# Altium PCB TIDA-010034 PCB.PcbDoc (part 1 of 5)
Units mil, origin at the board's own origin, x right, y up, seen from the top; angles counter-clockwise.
Board outline 4497.63 x 4881.81 mil, 4 copper layers (Top Layer, Signal Layer 1, Signal Layer 2, Bottom Layer), stack 62.18 mil thick; 483 components, 240 nets, 1255 pads, 589 vias.
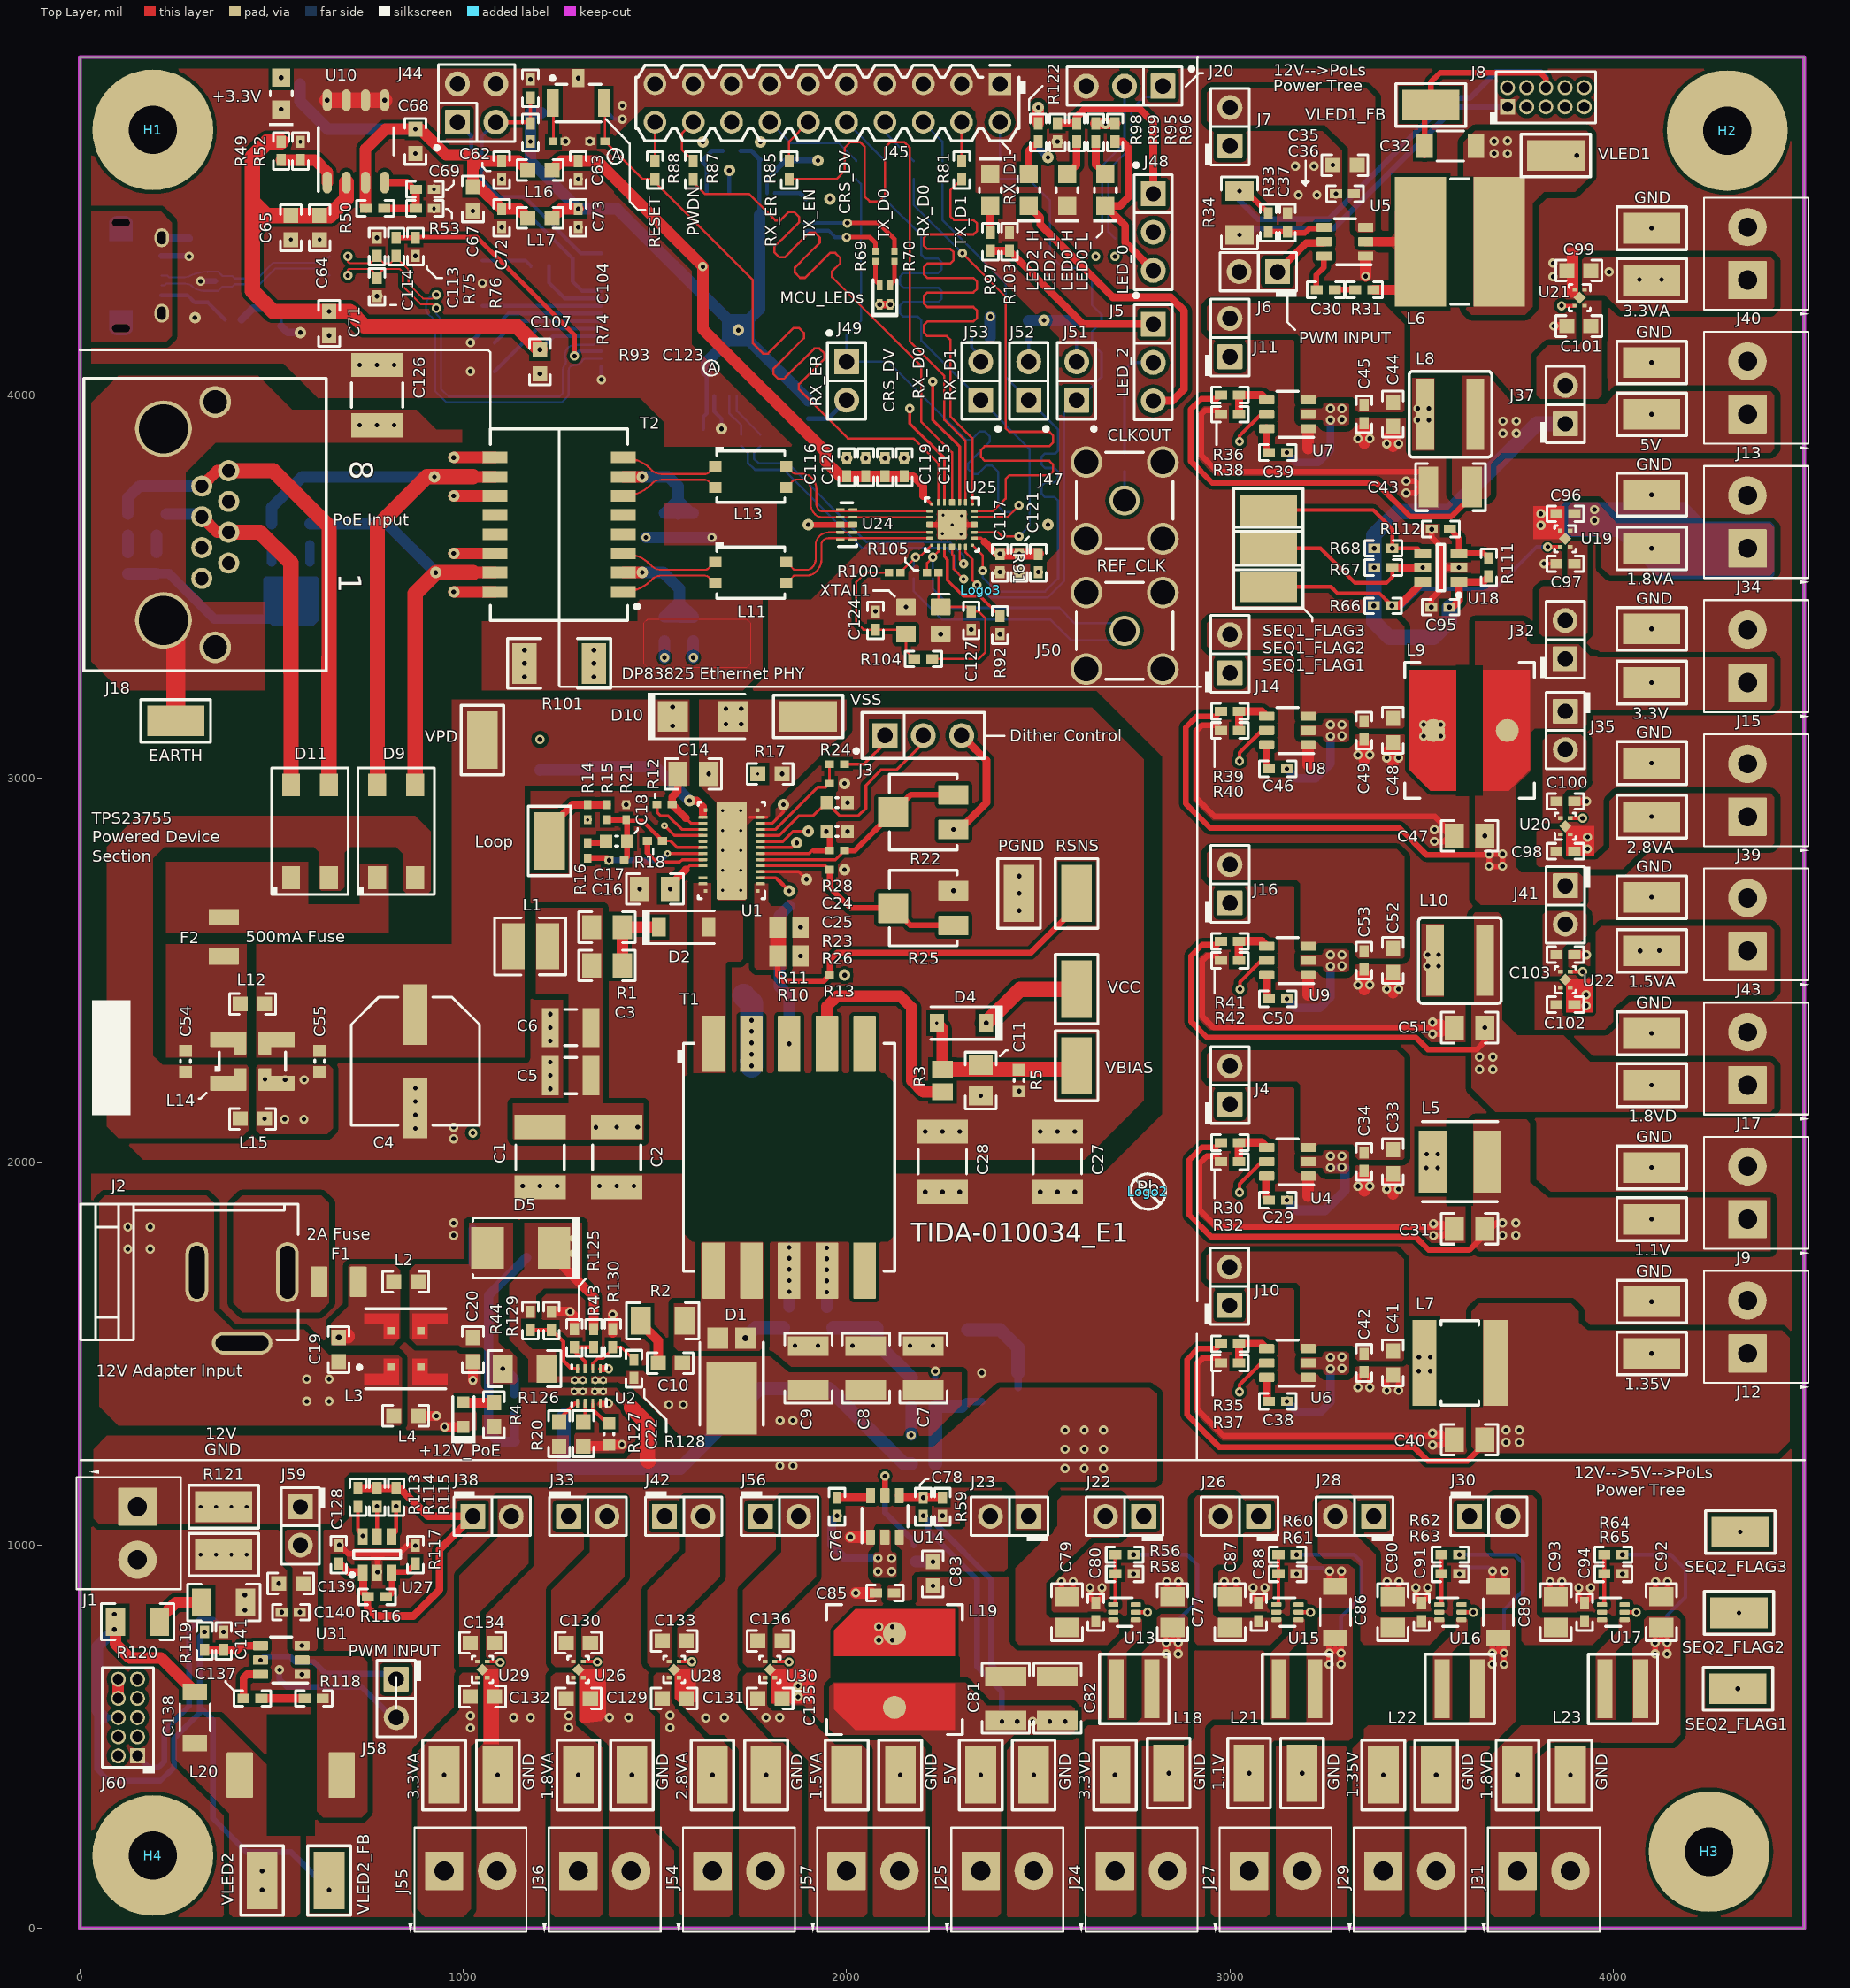
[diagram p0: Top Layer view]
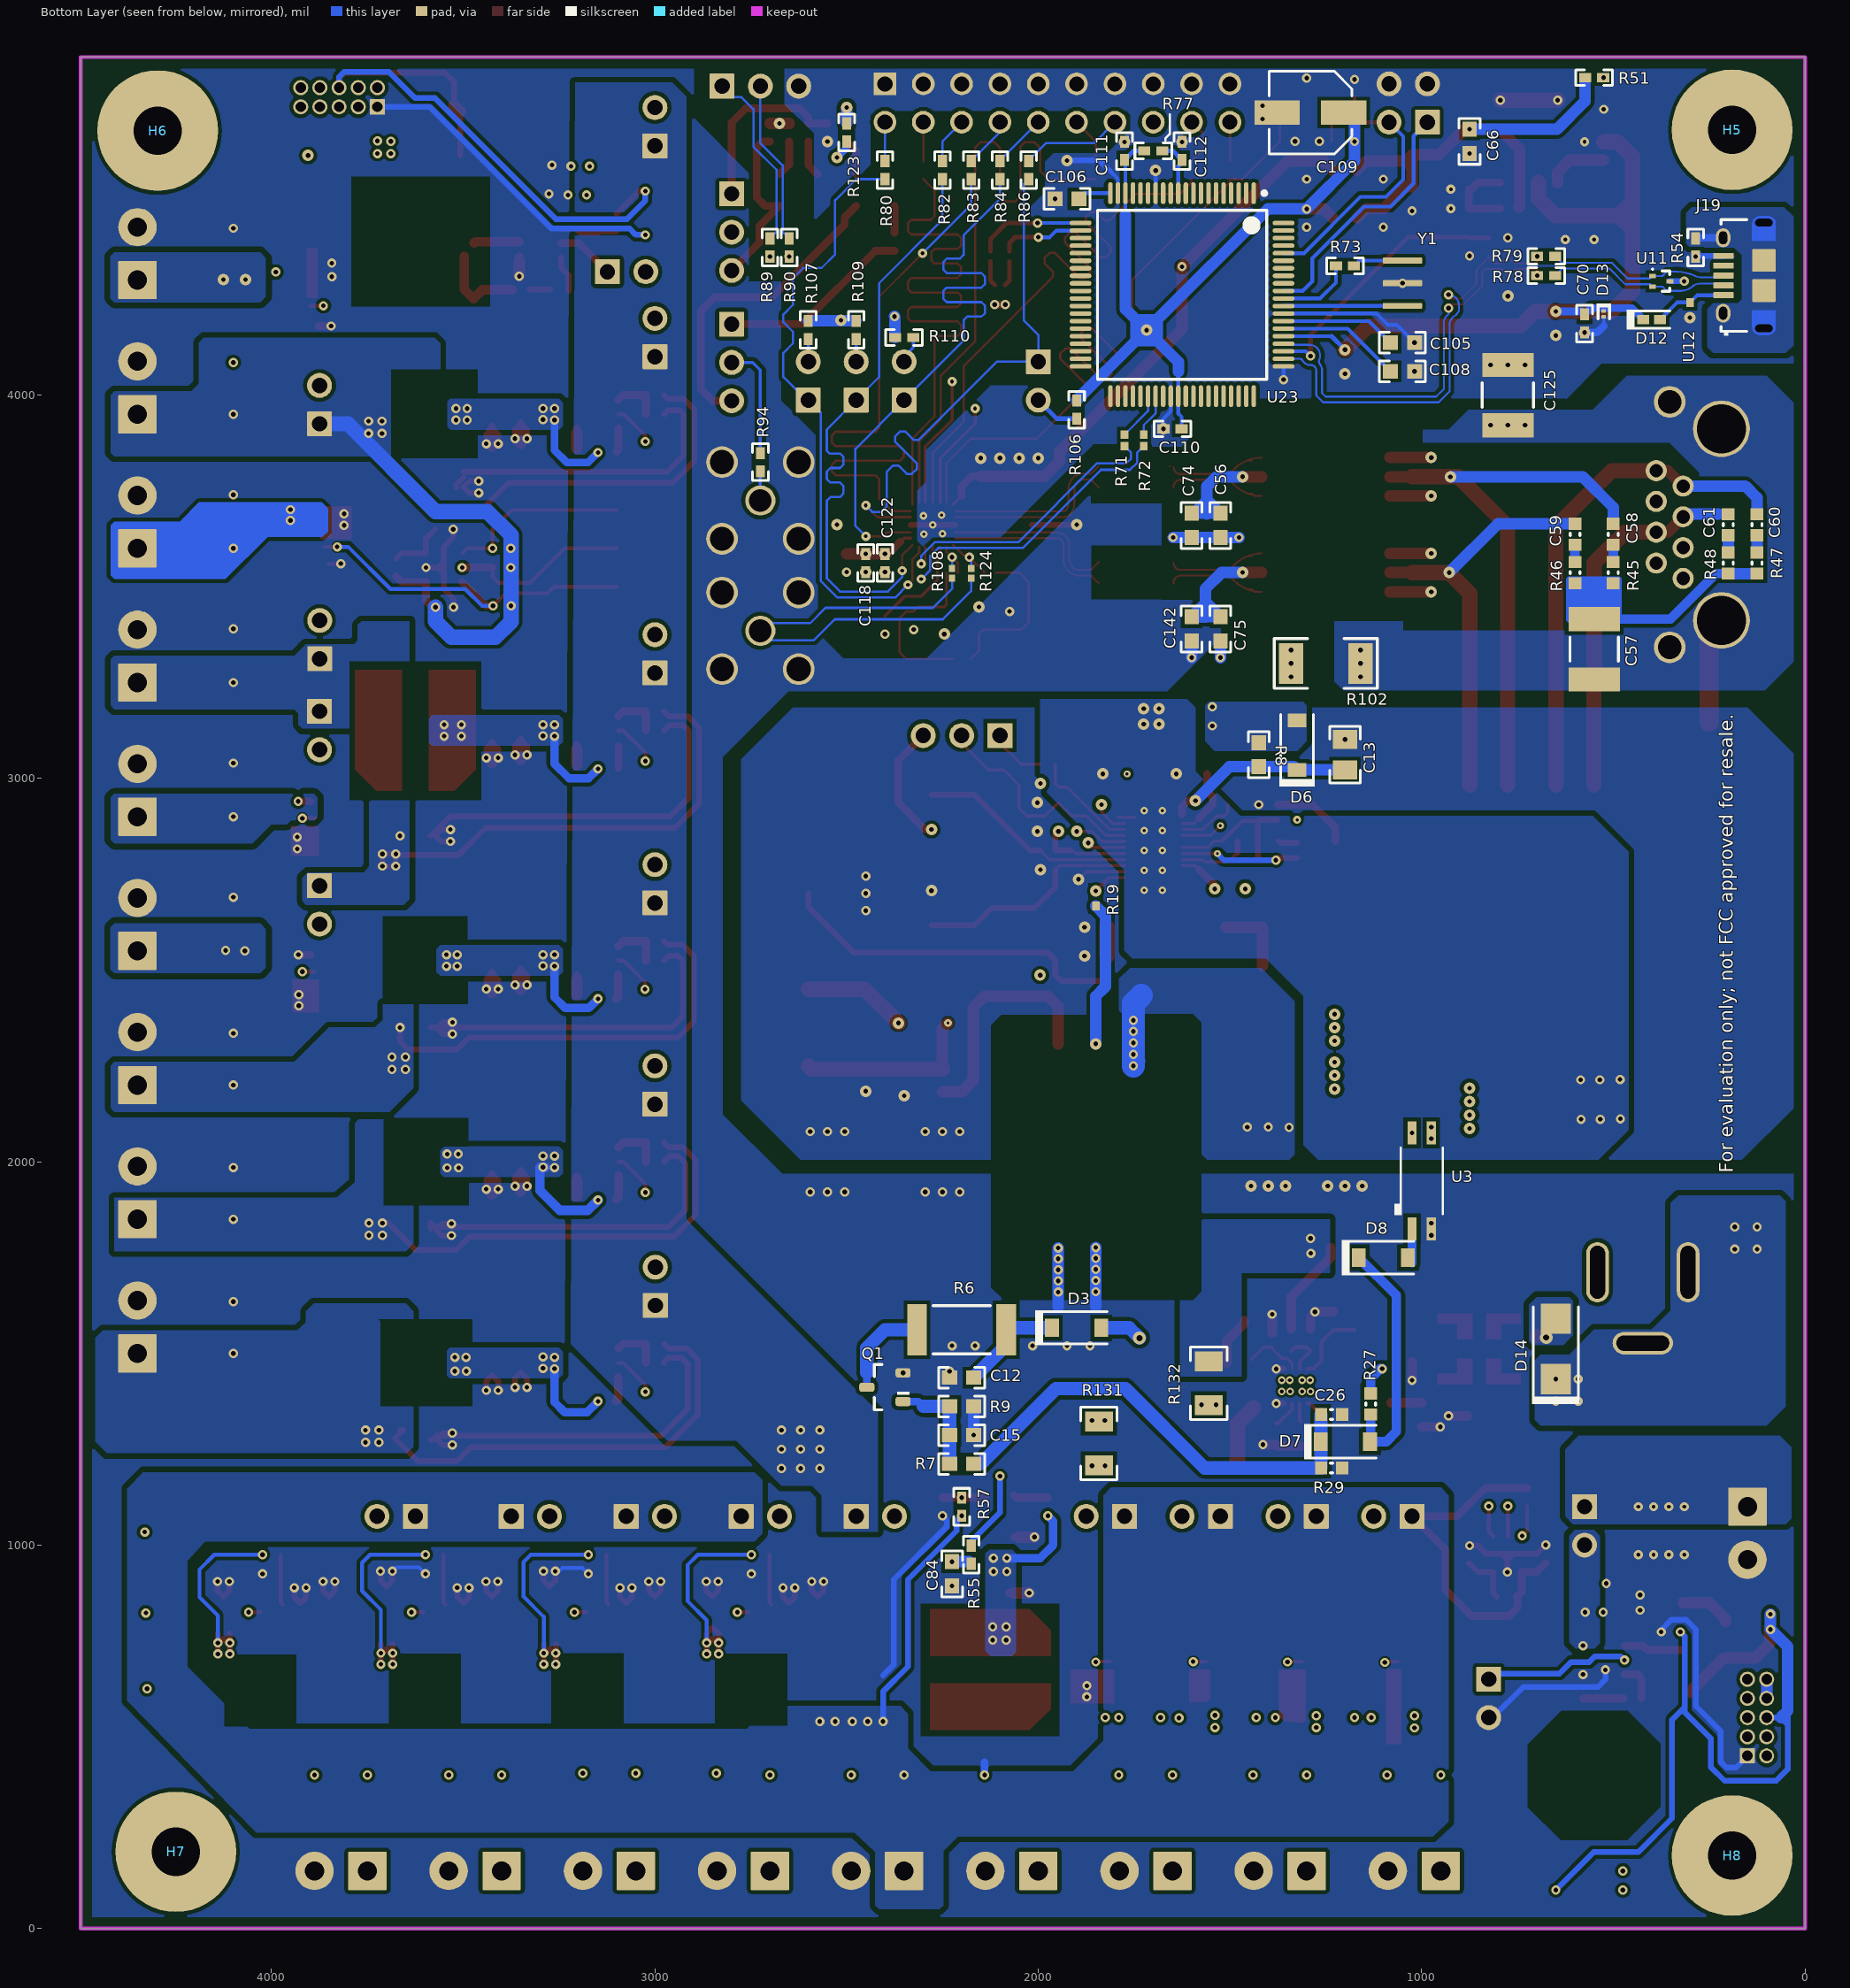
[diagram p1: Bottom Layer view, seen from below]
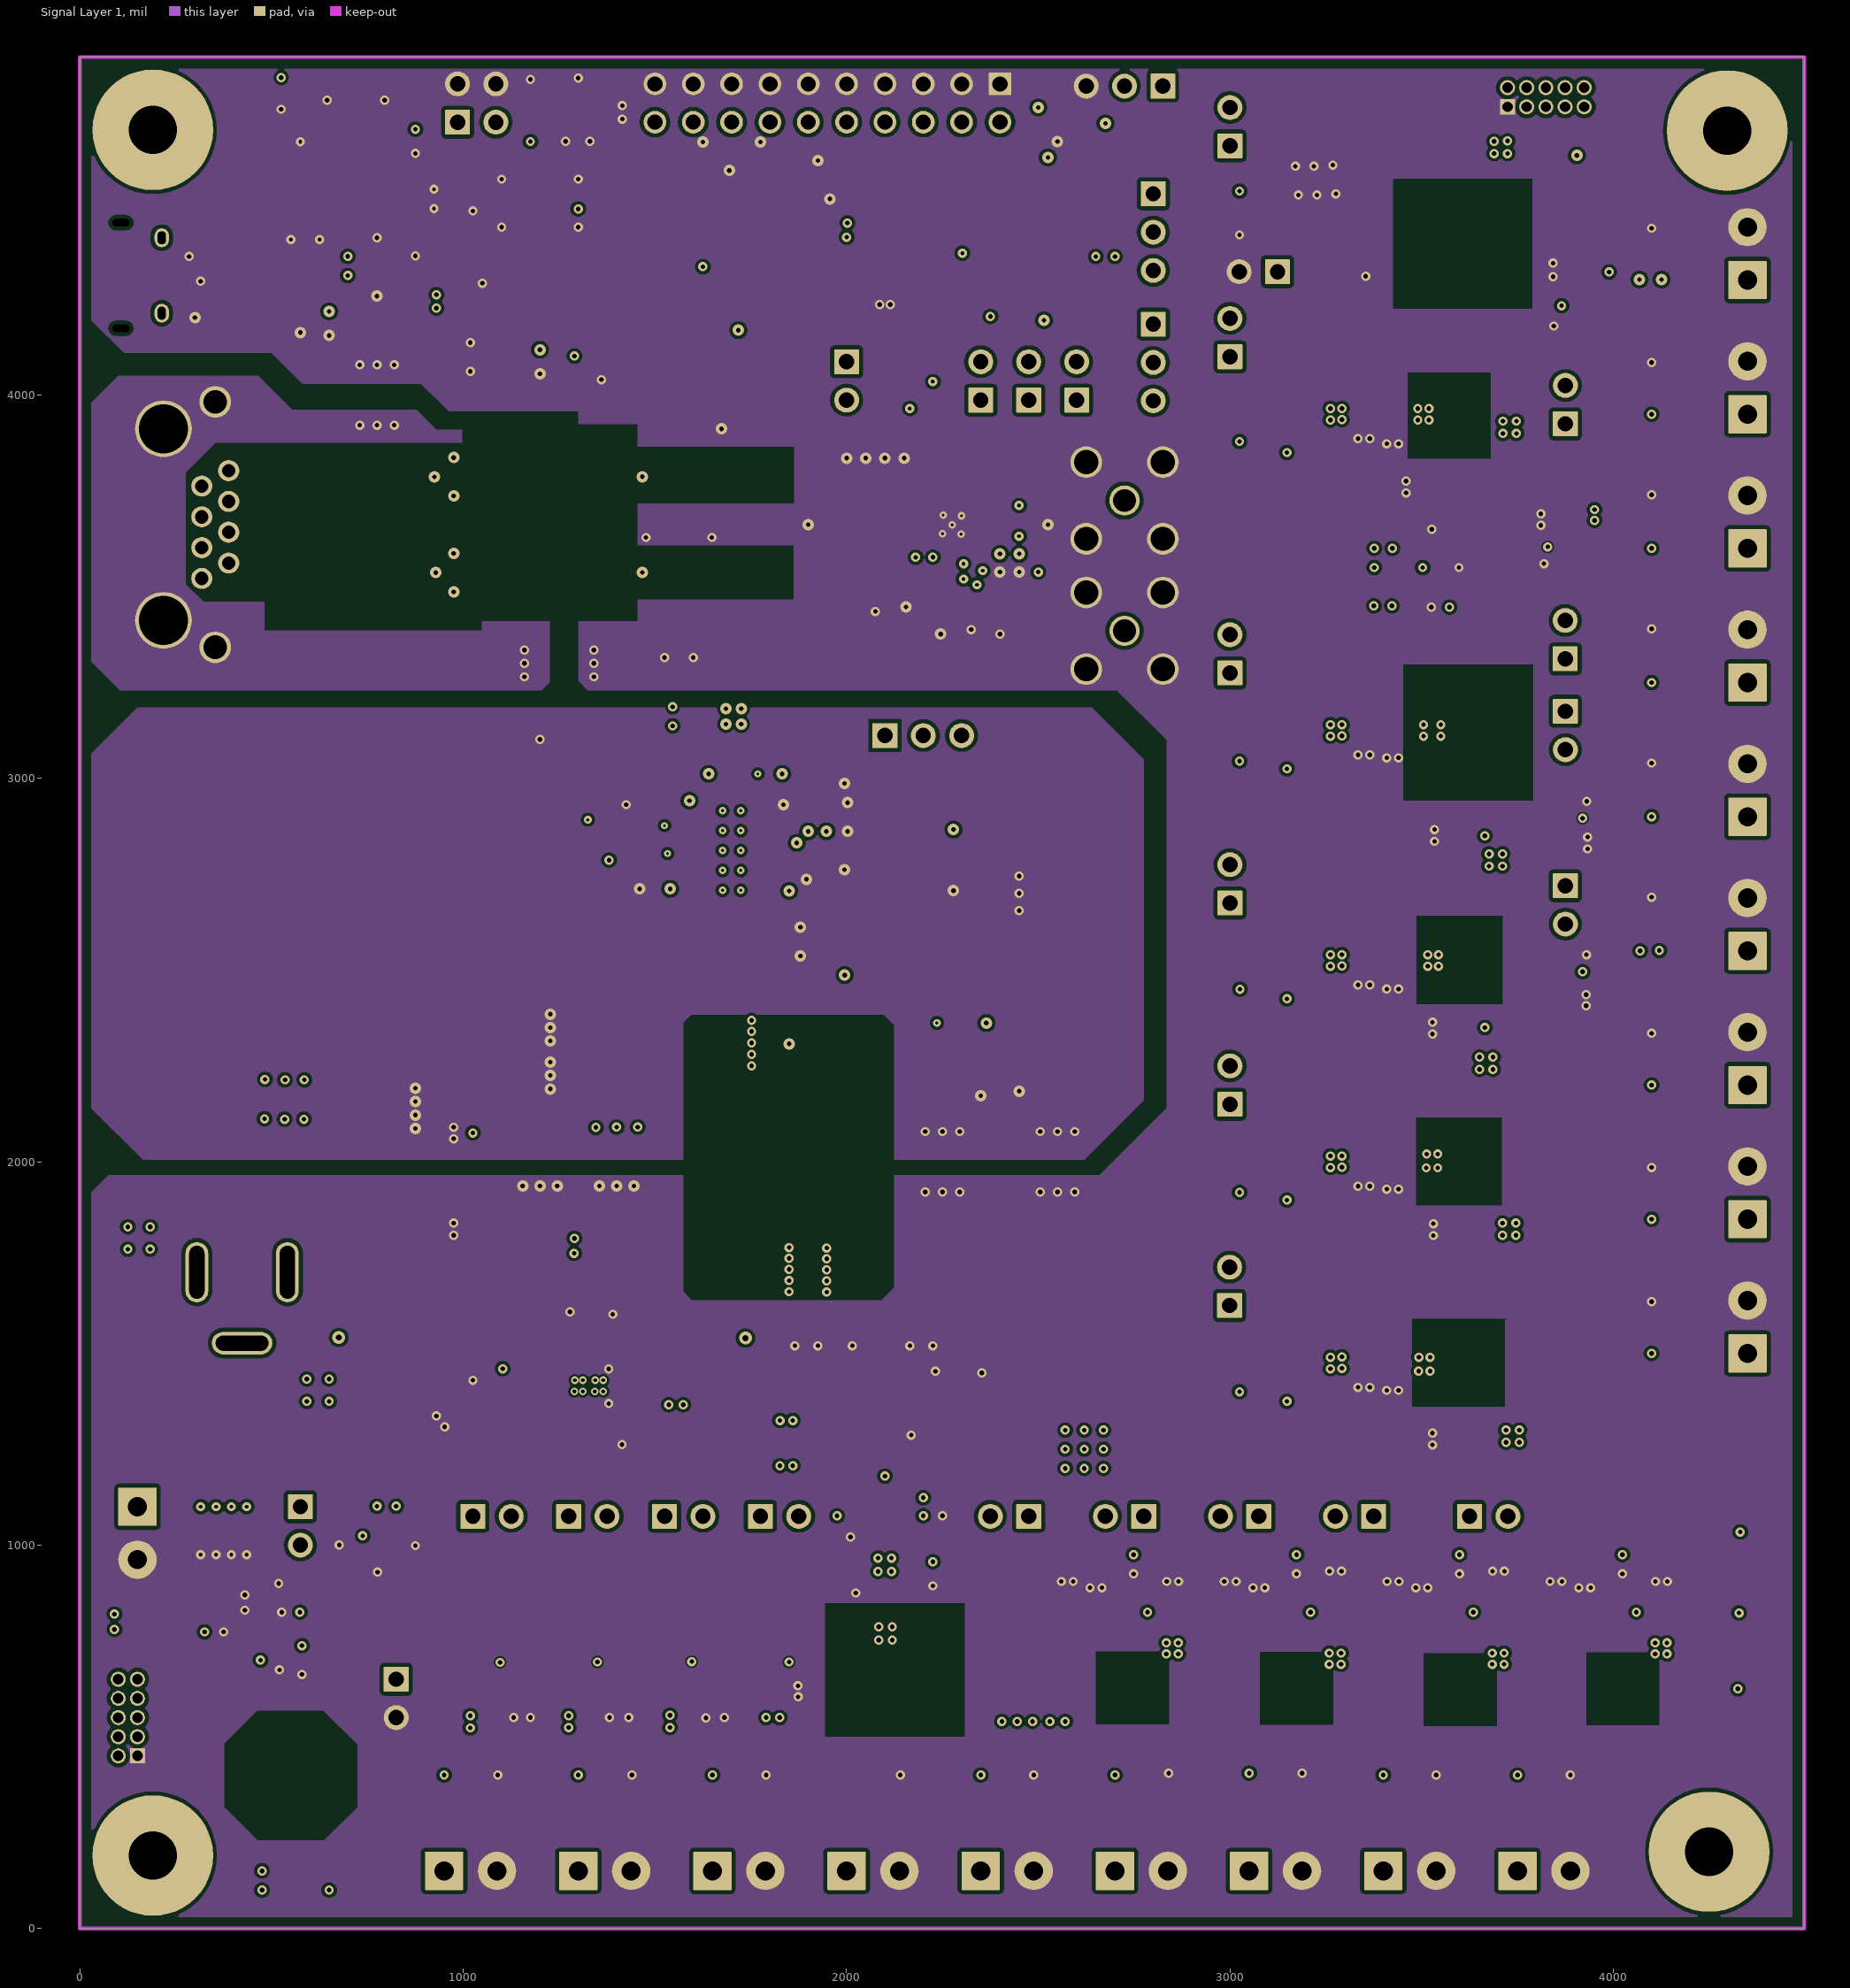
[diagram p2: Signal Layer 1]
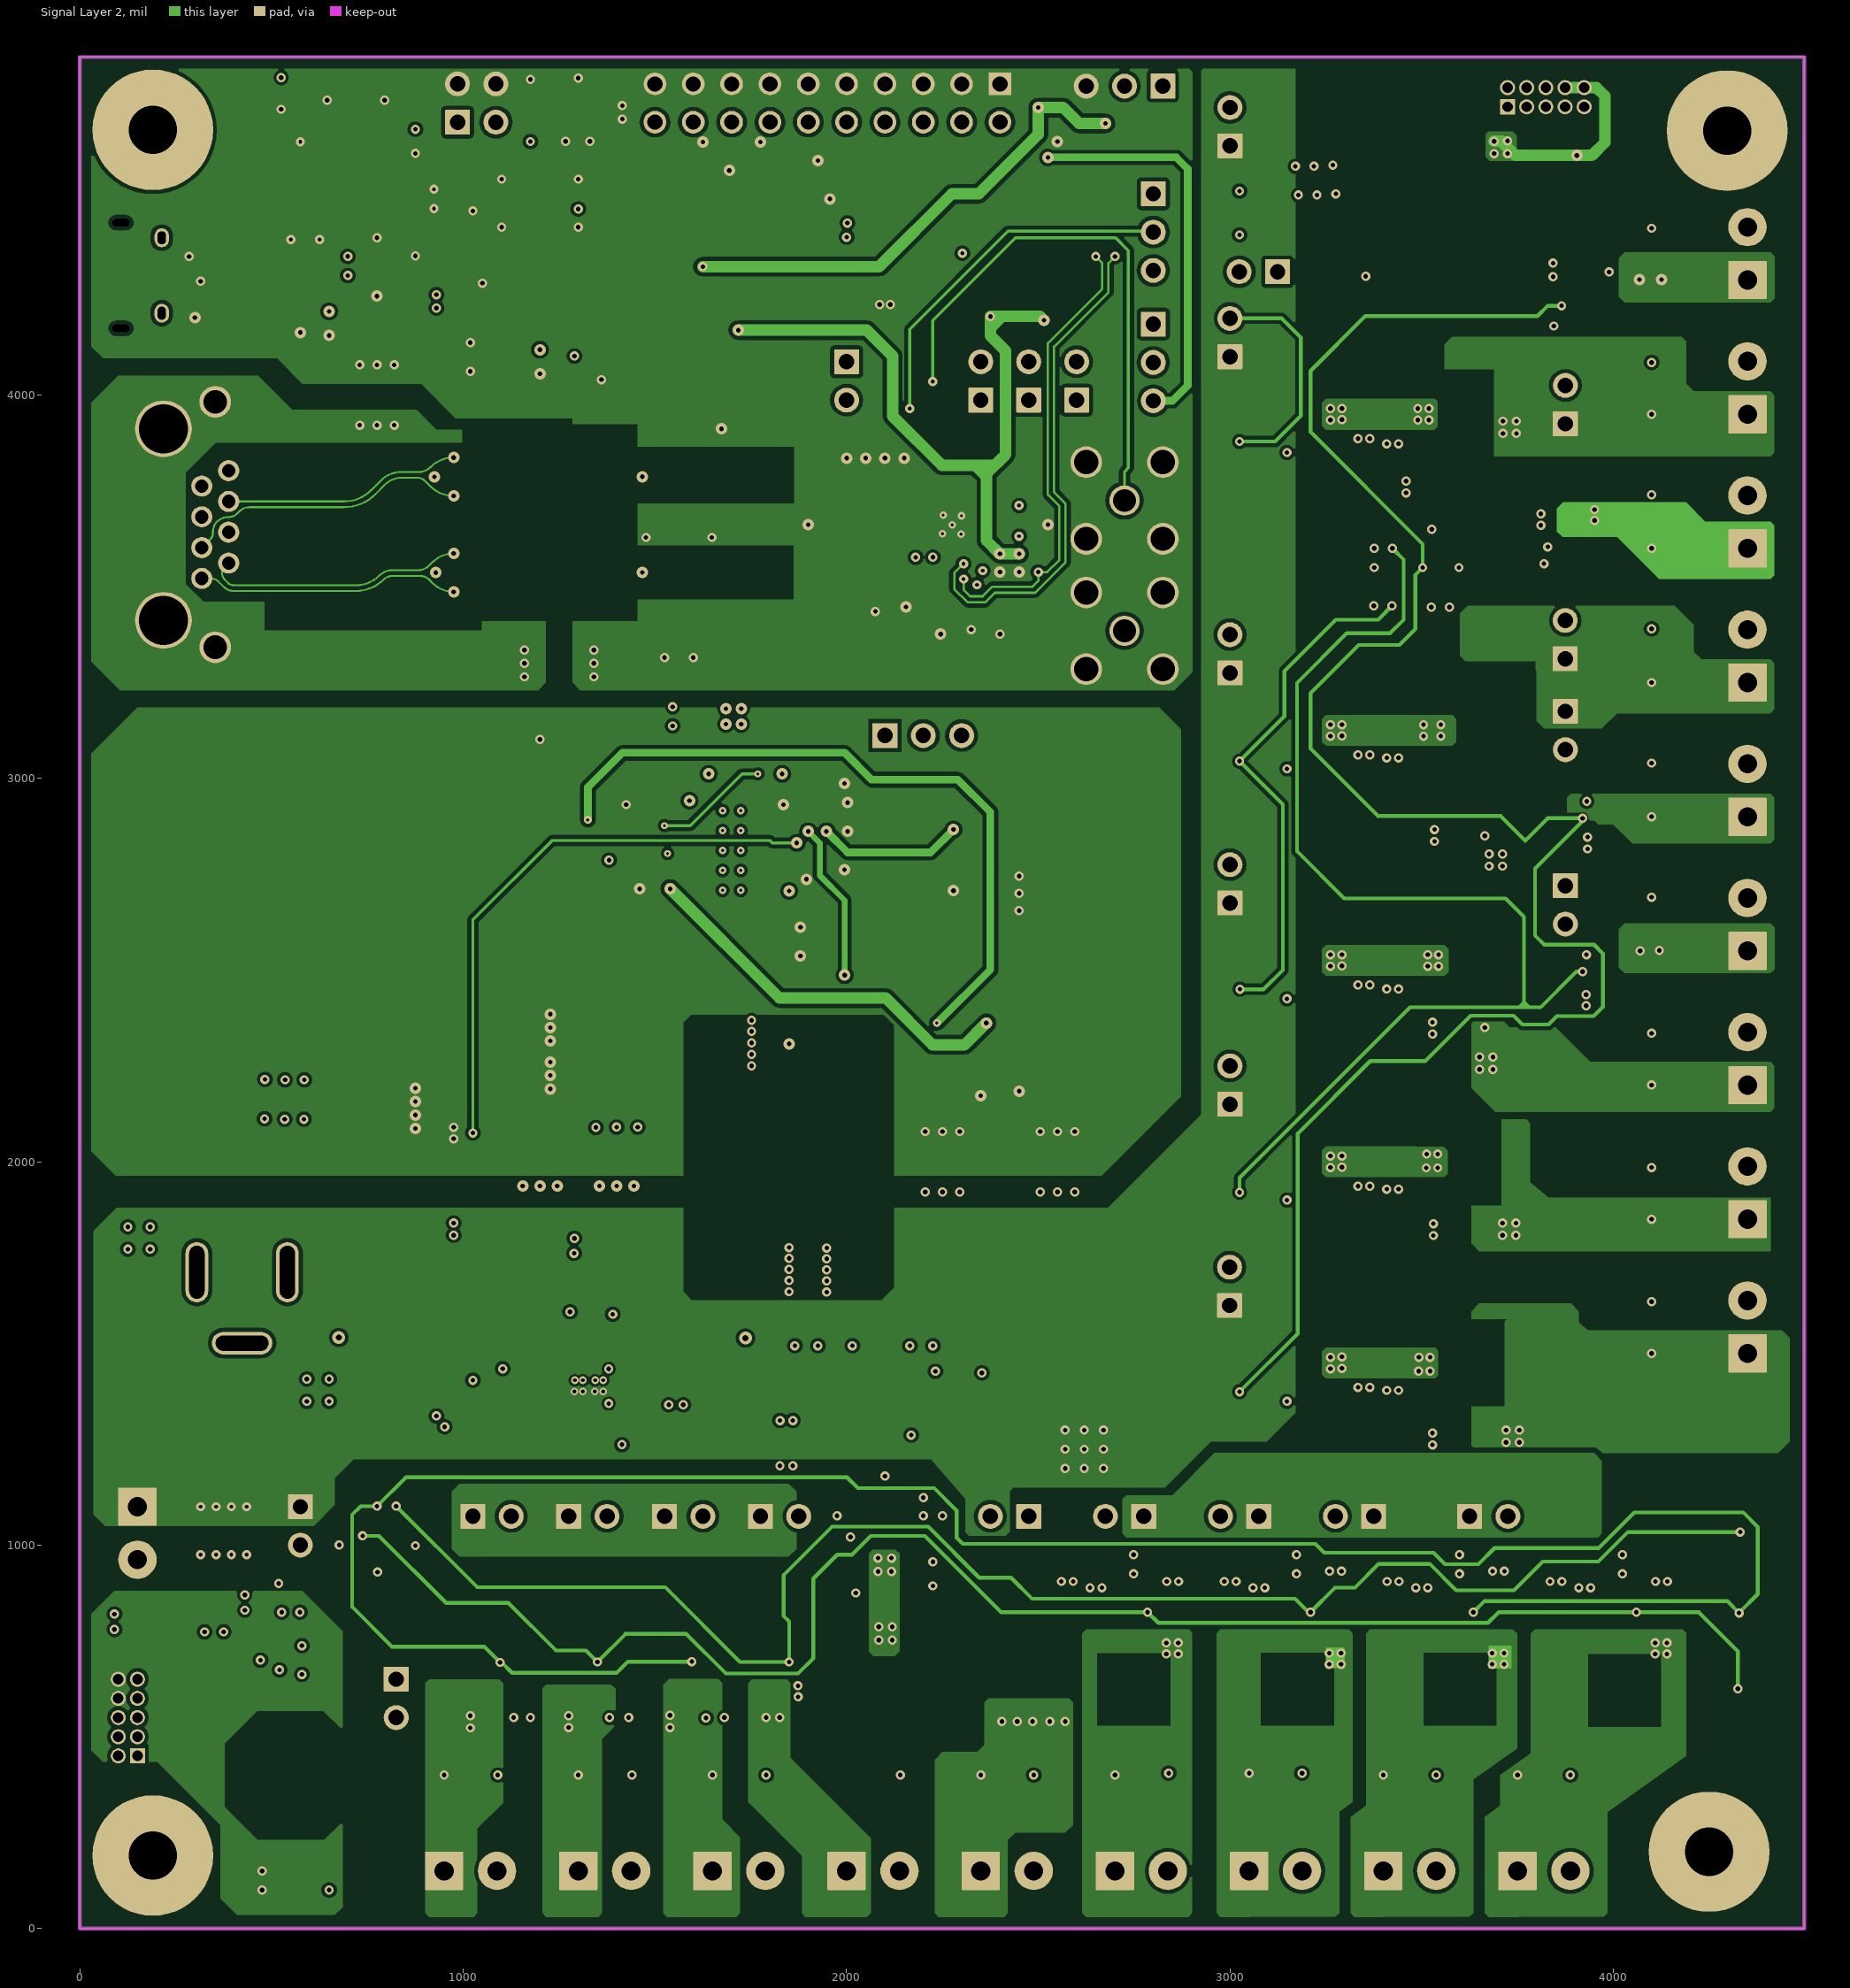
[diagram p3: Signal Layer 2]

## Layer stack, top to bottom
Top Solder: solder mask 0.4, Solder Resist, Dk 3.5
Top Layer: signal copper 1.89
Dielectric1: core 4.2, FR-4, Dk 4.8
Signal Layer 1: signal copper 1.378
Dielectric 2: core 47.244, FR-4, Dk 4.8
Signal Layer 2: signal copper 1.378
Dielectric 3: core 4.2, FR-4, Dk 4.8
Bottom Layer: signal copper 1.89
Bottom Solder: solder mask 0.4, Solder Resist, Dk 3.5

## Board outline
0,0 0,4881.81 4497.63,4881.81 4497.63,0

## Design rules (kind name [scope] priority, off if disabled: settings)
AcuteAngle [All] p1: minimum=4.50000000000000E+0001 checktracksonly=FALSE
AssemblyTestPointUsage [All] p1: valid=2
BoardOutlineClearance BoardOutlineClearance_MountingHoles [OnCopper and InComponentClass('Mounting Holes')] p1: gap=30 ignorepadtopadclearanceinfootprint=FALSE
BoardOutlineClearance BoardOutlineClearance_Poly [OnCopper and IsPoly] p2: gap=25 ignorepadtopadclearanceinfootprint=FALSE
BoardOutlineClearance [OnCopper and Not InComponentClass('Logo') and not InComponentClass('FiducialMark') and not InRegion(1000,500,4000,800) and not InPoly] p3: gap=25 ignorepadtopadclearanceinfootprint=FALSE
Clearance Clearance_U2 [WithinRoom('RoomDefinition_U2')] p1: gap=6 ignorepadtopadclearanceinfootprint=FALSE
Clearance Clearance_U19_U20_U21_U22 [WithinRoom('RoomDefinition_U21')or WithinRoom('RoomDefinition_U19')or WithinRoom('RoomDefinition_U20')or WithinRoom('RoomDefinition_U22')] p2: gap=4 ignorepadtopadclearanceinfootprint=FALSE
Clearance Clearance_U26_U28_U29_U30 [WithinRoom('RoomDefinition_U28')or WithinRoom('RoomDefinition_U30')or WithinRoom('RoomDefinition_U26')or WithinRoom('RoomDefinition_U29')] p3: gap=4 ignorepadtopadclearanceinfootprint=FALSE
Clearance Clearance_4 [InNet('PGND') And OnLayer('Multi-Layer')] p4: gap=10 ignorepadtopadclearanceinfootprint=FALSE except(0: Arc-Hole Track-Hole SMDPad-Hole THPad-Hole Via-Hole Fill-Hole Poly-Hole Region-Hole Text-Hole; 15: Poly-Poly)
Clearance "Keepout to all" [IsKeepOut] p5: gap=25 ignorepadtopadclearanceinfootprint=FALSE except(0: Arc-Hole Track-Hole SMDPad-Hole THPad-Hole Via-Hole Fill-Hole Poly-Hole Region-Hole Text-Hole)
Clearance Clearance_2 [InNamedPolygon('TOP_LAYER_DRAIN_P010')] p6: gap=10 ignorepadtopadclearanceinfootprint=FALSE except(0: Arc-Hole Track-Hole SMDPad-Hole THPad-Hole Via-Hole Fill-Hole Poly-Hole Region-Hole Text-Hole; 8: Via-Fill Via-Poly Via-Region; 15: Fill-Fill Fill-Poly Fill-Region Poly-Poly Poly-Region Region-Region)
Clearance Clearance_1 [InNamedPolygon('TOP_LAYER_RSNS_P008') And OnLayer('Top Layer')] p7: gap=10 ignorepadtopadclearanceinfootprint=FALSE except(0: Arc-Hole Track-Hole SMDPad-Hole THPad-Hole Via-Hole Fill-Hole Poly-Hole Region-Hole Text-Hole; 8: Via-Fill Via-Poly Via-Region; 15: Fill-Fill Fill-Poly Fill-Region Poly-Poly Poly-Region Region-Region)
Clearance Clearance_Keepouts [((IsTrack Or IsArc) And Not InPoly) And IsFree and IsKeepOut vs ((IsTrack Or IsArc) And Not InPoly) And IsFree and IsKeepOut] p8: gap=0 ignorepadtopadclearanceinfootprint=FALSE
Clearance Clearance_Poly [InPolygon] p9: gap=10 ignorepadtopadclearanceinfootprint=FALSE except(0: Arc-Hole Track-Hole SMDPad-Hole THPad-Hole Via-Hole Fill-Hole Poly-Hole Region-Hole Text-Hole; 8: Via-Poly; 15: Poly-Poly)
Clearance Clearance_FiducialMark [IsKeepOut and InComponentClass('FiducialMark') vs IsPad and InComponentClass('FiducialMark')] p10: gap=0 ignorepadtopadclearanceinfootprint=FALSE
Clearance [All] p11: gap=7.87 ignorepadtopadclearanceinfootprint=FALSE except(0: Arc-Hole Track-Hole SMDPad-Hole THPad-Hole Via-Hole Fill-Hole Poly-Hole Region-Hole Text-Hole; 4.7: SMDPad-SMDPad; 15: Fill-Fill Fill-Poly Fill-Region Poly-Poly Poly-Region Region-Region)
ComponentClearance ComponentClearance_MountingHoles_FiducialMarks [InComponentClass('Mounting Holes') vs InComponentClass('FiducialMark')] p1: gap=10 collisioncheckmode=3 verticalgap=10 showdistances=FALSE
ComponentClearance ComponentClearance_Shunt [InComponentClass('Header') vs InComponentClass('Shunt')] p2: gap=0 collisioncheckmode=3 verticalgap=0 showdistances=FALSE
ComponentClearance ComponentClearance_Logo [InComponentClass('Logo')] p3: gap=10 collisioncheckmode=3 verticalgap=10 showdistances=FALSE
ComponentClearance ComponentClearance_ScrewToNut [(HasFootprint('NY PMS 440 0025 PH')) vs (HasFootprint('Keystone_1902C'))] p4: gap=5 collisioncheckmode=3 verticalgap=10 showdistances=FALSE
ComponentClearance ComponentClearance_MountingHoles [InComponentClass('Mounting Holes')] p5: gap=10 collisioncheckmode=3 verticalgap=100000 showdistances=FALSE
ComponentClearance ComponentClearance_SmallPassives [HasFootprint('0201*') or HasFootprint('0402*') or HasFootprint('0508') or HasFootprint('0603*') or HasFootprint('0612') or HasFootprint('0805*') or HasFootprint('0815*') or HasFootprint('0830*') or HasFootprint('1206*') or HasFootprint('1210*') or HasFootprint('1808*') or HasFootprint('1812*') or HasFootprint('1825*') or HasFootprint('2010*') or HasFootprint('2220*') or HasFootprint('2225*') or HasFootprint('2512*') or HasFootprint('2728*') or HasFootprint('3518*') vs HasFootprint('0201*') or HasFootprint('0402*') or HasFootprint('0508') or HasFootprint('0603*') or HasFootprint('0612') or HasFootprint('0805*') or HasFootprint('0815*') or HasFootprint('0830*') or HasFootprint('1206*') or HasFootprint('1210*') or HasFootprint('1808*') or HasFootprint('1812*') or HasFootprint('1825*') or HasFootprint('2010*') or HasFootprint('2220*') or HasFootprint('2225*') or HasFootprint('2512*') or HasFootprint('2728*') or HasFootprint('3518*')] p6: gap=10 collisioncheckmode=3 verticalgap=10 showdistances=FALSE
ComponentClearance ComponentClearance_THtoSMT [IsThruComponent vs IsSMTComponent] p7: gap=10 collisioncheckmode=3 verticalgap=10 showdistances=FALSE
ComponentClearance ComponentClearance_THtoTH [IsThruComponent vs IsThruComponent] p8: gap=10 collisioncheckmode=3 verticalgap=10 showdistances=FALSE
ComponentClearance [All] p9: gap=10 collisioncheckmode=3 verticalgap=10 showdistances=FALSE
DiffPairsRouting [All] p1: maxlimit=10 minlimit=10 mostfreqgap=10 toplayer_minwidth=5 toplayer_maxwidth=5 toplayer_prefwidth=5 midlayer1_minwidth=5 midlayer1_maxwidth=5 midlayer1_prefwidth=5 midlayer2_minwidth=5 midlayer2_maxwidth=5 midlayer2_prefwidth=5 bottomlayer_minwidth=5 bottomlayer_maxwidth=5 bottomlayer_prefwidth=5 maxuncoupledlength=1000
FabricationTestPointUsage TestPointUsage [All] p1: valid=2 allowmultiple=FALSE
FabricationTestpoint Testpoint [All] p1: side=3 testpointundercomponent=TRUE minsize=40 maxsize=100 preferedsize=60 minholesize=0 maxholesize=40 preferedholesize=32 testpointgrid=1 allowsidetop=TRUE allowsidebottom=TRUE usegrid=TRUE gridtolerance=0.01
FanoutControl Fanout_LCC [IsLCC] p1: bgadir=Out bgaviamode=Centered fanoutstyle=Auto fanoutdirection=Alternating viagrid=1 // Fanout_LCC (Default Rule)
FanoutControl Fanout_BGA [IsBGA] p2: bgadir=Out bgaviamode=Centered fanoutstyle=Auto fanoutdirection=Alternating viagrid=1 // Fanout_BGA (Default Rule)
FanoutControl Fanout_Default [All] p4: bgadir=Out bgaviamode=Centered fanoutstyle=Auto fanoutdirection=Alternating viagrid=1 // Fanout_Default (Default Rule)
FanoutControl Fanout_Small [(CompPinCount < 5)] p5: bgadir=Out bgaviamode=Centered fanoutstyle=Auto fanoutdirection=OutThenIn viagrid=1 // Fanout_Small (Default Rule)
HoleSize [All] p1: absolutevalues=TRUE maxlimit=251 minlimit=7.87 maxpercent=80.000 minpercent=20.000
MatchedLengths "Length Matching" [InNetClass('Length match')] p1: tolerance=20 checknetsindiffpair=FALSE checkdiffpairvsdiffpair=TRUE checkxsignals=TRUE checkothers=TRUE
MinimumAnnularRing MinimumAnnularRing_ThermalPadVias [IsVia and InAnyComponent] p1: minimumring=5.91
MinimumAnnularRing [All] p2: minimumring=8
MinimumSolderMaskSliver MinimumSolderMaskSliver_Logo [InComponentClass('Logo') vs InComponentClass('Logo')] p1: minsoldermaskwidth=0.7
MinimumSolderMaskSliver [All] p2: minsoldermaskwidth=3.94
PlaneConnect [All] p1: planeconnectstyle=Relief reliefexpansion=10 reliefentries=4 reliefconductorwidth=10 reliefairgap=10
PolygonConnect [All] p1: connectstyle=Direct reliefconductorwidth=10 reliefentries=4 polygonreliefangle="90 Angle" airgapwidth=10
RoomDefinition RoomDefinition_U2 [All] p1: confinementstyle=ConfineOut formatcopy=TRUE lockcomponents=FALSE outline 1400,1350 1250,1350 1250,1480 1400,1480
RoomDefinition [All vs False] p2: confinementstyle=ConfineOut formatcopy=TRUE lockcomponents=FALSE outline 1250,1480.41
RoomDefinition RoomDefinition_U22 [All] p3: confinementstyle=ConfineOut formatcopy=TRUE lockcomponents=FALSE outline 3840,2510 3919.72,2510 3919.72,2430 3840,2430
RoomDefinition RoomDefinition_U20 [All] p4: confinementstyle=ConfineOut formatcopy=TRUE lockcomponents=FALSE outline 3840,2915 3929.88,2915 3929.88,2840 3840,2840
RoomDefinition RoomDefinition_U19 [InComponentClass('Components Class 4')] p5: confinementstyle=ConfineIn formatcopy=TRUE lockcomponents=FALSE outline 3820,3664.71 3926,3664.71 3926,3580 3820,3580
RoomDefinition RoomDefinition_U21 [InComponentClass('Components Class 3')] p6: confinementstyle=ConfineIn formatcopy=TRUE lockcomponents=FALSE outline 3870,4298.62 3955,4298.62 3955,4210 3870,4210
RoomDefinition RoomDefinition_U30 [All] p7: confinementstyle=ConfineOut formatcopy=TRUE lockcomponents=FALSE outline 1740,720 1865,720 1865,640 1740,640
RoomDefinition RoomDefinition_U28 [All] p8: confinementstyle=ConfineOut formatcopy=TRUE lockcomponents=FALSE outline 1500,720 1610,720 1610,640 1500,640
RoomDefinition RoomDefinition_U26 [InComponentClass('Components Class 2')] p9: confinementstyle=ConfineIn formatcopy=TRUE lockcomponents=FALSE outline 1240.02,720 1369.69,720 1369.69,630 1240.02,630
RoomDefinition RoomDefinition_U29 [InComponent('U29')] p10: confinementstyle=ConfineOut formatcopy=TRUE lockcomponents=FALSE outline 982,620 1125.16,620 1125.16,721 982,721
RoutingVias ThermalPadVias [IsVia and InAnyComponent] p1: holewidth=7.87 width=19.68 viastyle="Through Hole" minholewidth=7.87 minwidth=19.68 maxholewidth=12.99 maxwidth=23.62
RoutingVias [All] p2: holewidth=12 width=24 viastyle="Through Hole" minholewidth=7.87 minwidth=20 maxholewidth=40 maxwidth=65
SilkToBoardRegionClearance [Not ((IsComment or IsDesignator) And (Hide <> 'False')) and not InRegion(1000,500,4000,800)] p1:
SilkToSilkClearance SilkToSilkClearance_Pb-FreeLogo [(HasFootprint('Pb-Free_Overlay_Medium') OR HasFootprint('Pb-Free_Overlay_Small')) vs (HasFootprint('Pb-Free_Overlay_Medium') OR HasFootprint('Pb-Free_Overlay_Small'))] p1: silktosilkclearance=0
SilkToSilkClearance [All] p2: silktosilkclearance=4
SilkToSolderMaskClearance SilkToComponentPadClearance [(IsPad or IsFill or IsRegion) and InAnycomponent] p1: minsilkscreentomaskgap=5 clearancetoexposedcopper=TRUE
SilkToSolderMaskClearance "Silk to Solder Mask Opening" [All] p2: minsilkscreentomaskgap=4 clearancetoexposedcopper=FALSE
SolderMaskExpansion [All] p1: expansion=1.97
Width [All] p1: maxlimit=100 minlimit=5 preferedwidth=10 minimp=50.000000 maximp=50.000000 favimp=50.000000 checkconnectedcopper=TRUE
15 further rules are at their usual default settings.

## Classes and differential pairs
net class Undefined: 12V
net class "Length match": CRS_DV_S PWDN_S RESET_S RX_D0_S RX_D1_S RX_ER_S TX_D0_S TX_D1_S TX_EN_S
component class "TIDA-010034 DP83825 ETHERNET PHY": C115 C116 C117 C118 C119 C120 C121 C122 C123 C124 C127 J5 J20 J45 J47 J48 J49 J50 J51 J52 J53 LED0_H LED0_L LED2_H LED2_L R80 R81 R82 R83 R84 R85 R86 R87 R88 R89 R90 R91 R92 R93 R94 R95 R96 R97 R98 R99 R100 R103 R104 R105 R106 R107 R108 R109 R110 R122 R123 R124 RESET U24 U25 XTAL1
component class "TIDA-010034 MSP430": C104 C105 C106 C107 C108 C109 C110 C111 C112 C113 C114 J44 MCU_LEDs R69 R70 R71 R72 R73 R74 R75 R76 R77 R78 R79 U23 Y1
component class "Mounting Holes": H1 H2 H3 H4
component class "TIDA-010034 Hardware": H1 H2 H3 H4 H5 H6 H7 H8 Logo2 Logo3 ZZ1 ZZ2 ZZ3 ZZ4
component class AssemblyNote: ZZ1 ZZ2 ZZ3 ZZ4
component class Header: J3 J4 J5 J6 J7 J8 J10 J11 J14 J16 J20 J22 J23 J26 J28 J30 J32 J33 J35 J37 J38 J41 J42 J44 J45 J48 J49 J51 J52 J53 J56 J58 J59 J60
component class "TIDA-010034 TPS23755 PD FRONT-END": 12V +12V_PoE C1 C2 C3 C4 C5 C6 C7 C8 C9 C10 C11 C12 C13 C14 C15 C16 C17 C18 C19 C20 C22 C24 C25 C26 C27 C28 D1 D2 D3 D4 D5 D6 D7 D8 D14 F1 GND J1 J2 J3 L1 L2 L3 L4 Loop PGND Q1 R1 R2 R3 R4 R5 R6 R7 R8 R9 R10 R11 R12 R13 R14 R15 R16 R17 R18 R19 R20 R21 R22 R23 R24 R25 R26 R27 R28 R29 R43 R44 R125 R126 R127 R128 R129 R130 R131 R132 RSNS T1 U1 U2 U3 VBIAS VCC
component class "TIDA-010034 PoE INPUT": C54 C55 C56 C57 C58 C59 C60 C61 C74 C75 C125 C126 C142 D9 D10 D11 EARTH F2 J18 L11 L12 L13 L14 L15 R45 R46 R47 R48 R101 R102 T2 VPD VSS
component class "TIDA-010034 12V To POINT OF LOADS": 1.1V 1.5VA 1.8VA 1.8VD 1.35V 2.8VA 3.3V 3.3VA 5V C29 C30 C31 C32 C33 C34 C35 C36 C37 C38 C39 C40 C41 C42 C43 C44 C45 C46 C47 C48 C49 C50 C51 C52 C53 C95 C96 C97 C98 C99 C100 C101 C102 C103 GND J4 J6 J7 J8 J9 J10 J11 J12 J13 J14 J15 J16 J17 J32 J34 J35 J37 J39 J40 J41 J43 L5 L6 L7 L8 L9 L10 R30 R31 R32 R33 R34 R35 R36 R37 R38 R39 R40 R41 R42 R66 R67 R68 R111 R112 SEQ1_FLAG1 SEQ1_FLAG2 SEQ1_FLAG3 U4 U5 U6 U7 U8 U9 U18 U19 U20 U21 U22 VLED1 VLED1_FB
net class Power: VDD1_1.1V VDD1_1.8V_codec VDD1_1.35V VDD1_3.3V VDD1_5V VDD2_1.1V VDD2_1.8V_Codec VDD2_1.35V VDD2_3.3V VDD2_5V
component class "TIDA-010034 12V TO 5V TO POINT OF LOADS": 1.1V 1.5VA 1.8VA 1.8VD 1.35V 2.8VA 3.3VA 3.3VD 5V C76 C77 C78 C79 C80 C81 C82 C83 C84 C85 C86 C87 C88 C89 C90 C91 C92 C93 C94 C128 C129 C130 C131 C132 C133 C134 C135 C136 C137 C138 C139 C140 C141 GND J22 J23 J24 J25 J26 J27 J28 J29 J30 J31 J33 J36 J38 J42 J54 J55 J56 J57 J58 J59 J60 L18 L19 L20 L21 L22 L23 R55 R56 R57 R58 R59 R60 R61 R62 R63 R64 R65 R113 R114 R115 R116 R117 R118 R119 R120 R121 SEQ2_FLAG1 SEQ2_FLAG2 SEQ2_FLAG3 U13 U14 U15 U16 U17 U26 U27 U28 U29 U30 U31 VLED2 VLED2_FB
component class "TIDA-010034 USB INPUT": +3.3V C62 C63 C64 C65 C66 C67 C68 C69 C70 C71 C72 C73 D12 D13 J19 L16 L17 R49 R50 R51 R52 R53 R54 U10 U11 U12
differential pair USB: +USB_P -USB_N
differential pair TD: +TD_P -TD_N
differential pair TARGET_D: +TARGET_D_P -TARGET_D_N
differential pair RD: +RD_P -RD_N
differential pair "netj18_1 & 2": +NetJ18_1 -NetJ18_2
differential pair "NetJ18_3 & 6": +NetJ18_3 -NetJ18_6

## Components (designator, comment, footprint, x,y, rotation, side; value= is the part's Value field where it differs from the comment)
1.1V "TESTPOINT" Keystone_5019 4100,1850 r0 top
1.1V "TESTPOINT" Keystone_5019 3050,405 r270 top
1.5VA "TESTPOINT" Keystone_5019 2000,400 r90 top
1.5VA "TESTPOINT" Keystone_5019 4100,2550 r180 top
1.8VA "TESTPOINT" Keystone_5019 1300,400 r90 top
1.8VA "TESTPOINT" Keystone_5019 4100,3600 r180 top
1.8VD "TESTPOINT" Keystone_5019 4100,2200 r180 top
1.8VD "TESTPOINT" Keystone_5019 3750,400 r270 top
1.35V "TESTPOINT" Keystone_5019 4100,1500 r0 top
1.35V "TESTPOINT" Keystone_5019 3400,400 r270 top
2.8VA "TESTPOINT" Keystone_5019 1650,400 r90 top
2.8VA "TESTPOINT" Keystone_5019 4100,2900 r180 top
3.3V "TESTPOINT" Keystone_5019 4100,3250 r180 top
3.3VA "TESTPOINT" Keystone_5019 950,400 r90 top
3.3VA "TESTPOINT" Keystone_5019 4100,4300 r180 top
3.3VD "TESTPOINT" Keystone_5019 2700,400 r270 top
5V "TESTPOINT" Keystone_5019 4100,3950 r0 top
5V "TESTPOINT" Keystone_5019 2350,400 r90 top
12V "TESTPOINT" Keystone_5019 375,1100 r0 top
+3.3V "QTLP630C4TR" QTLP630C_Green 525,4786.81 r270 top value=Green
+12V_PoE "150060YS75000" WL-SMCW_YELLOW 1000,1340 r90 top value=Yellow
C1 "C4532X7R3D222K130KA" 1812 1200,2011.81 r270 top value=2200pF
C2 "C4532X7R3D222K130KA" 1812 1400,2011.81 r270 top value=2200pF
C3 "C2012X7R2A104K125AA" 0805_HV 1375,2511.81 r0 top value=0.1uF
C4 "EEE-2AA100UP" SM_RADIAL_E 875,2261.81 r270 top value=10uF
C5 "GRM32ER72A225KA35L" 1210_270L 1280,2225 r180 top value=2.2uF
C6 "GRM32ER72A225KA35L" 1210_270L 1280,2350 r180 top value=2.2uF
C7 "GRM32ER71E226KE15L" 1210_270 2200,1461.81 r90 top value=22uF
C8 "GRM32ER71E226KE15L" 1210_270 2050,1461.81 r90 top value=22uF
C9 "GRM32ER71E226KE15L" 1210_270 1900,1461.81 r90 top value=22uF
C10 "06031C681KAT2A" 0603 1540,1475 r180 top value=680pF
C11 "GRM21BR71H105KA12L" 0805_HV 2350,2211.81 r270 top value=1uF
C12 "06035C104KAT2A" 0603 2200,1436.81 r180 bottom value=0.1uF
C13 "GRM21AR72A224KAC5L" 0805_HV 1200,3061.81 r90 bottom value=0.22uF
C14 "C2012X7R2A104K125AA" 0805_HV 1600,3011.81 r0 top value=0.1uF
C15 "06035C104KAT2A" 0603 2200,1286.81 r180 bottom value=0.1uF
C16 "GRM21BR71H105KA12L" 0805_HV 1500,2711.81 r180 top value=1uF
C17 "885012005061" 0402L 1400,2786.81 r0 top value=100pF
C18 "06031C103MAT2A" 0603L 1400,2836.81 r0 top value=0.01uF
C19 "GRM188R72A102KA01D" 0603 675,1510 r270 top value=1000pF
C20 "GRM188R72A102KA01D" 0603 1025,1510 r270 top value=1000pF
C22 "C1608X7R1E104K080AA" 0603L 1380,1290 r270 top value=0.1uF
C24 "GRM188R71H222KA01D" 0603L 1975,2936.81 r0 top value=2200pF
C25 "C1608X7R1E104K080AA" 0603L 1975,2861.81 r0 top value=0.1uF
C26 "06035C104KAT2A" 0603L 1235,1340.44 r180 bottom value=0.1uF
C27 "C4532X7R3D222K130KA" 1812 2550,2000 r270 top value=2200pF
C28 "C4532X7R3D222K130KA" 1812 2250,2000 r270 top value=2200pF
C29 "GRM155R71A104KA01D" 0402 3125,1900 r180 top value=0.1uF
C30 "GRM155R71A104KA01D" 0402 3250,4275 r180 top value=0.1uF
C31 "C2012X5R1A476M125AC" 0805_HV 3625,1825 r180 top value=47uF
C32 "C3216X5R1E336M160AC" 1206_180 3575,4650 r180 top value=33uF
C33 "GRM188R61E106MA73D" 0603 3425,2000 r270 top value=10uF
C34 "GRM155R71E104KE14D" 0402 3350,2000 r270 top value=0.1uF
C35 "GRM188R61E106MA73D" 0603 3300,4600 r180 top value=10uF
C36 "GRM155R71E104KE14D" 0402 3300,4525 r180 top value=0.1uF
C37 "GRM155R71A823KA01D" 0402 3150,4450 r90 top value=0.082uF
C38 "GRM155R71A104KA01D" 0402 3125,1375 r180 top value=0.1uF
C39 "GRM155R71A104KA01D" 0402 3125,3850 r180 top value=0.1uF
C40 "C2012X5R1A476M125AC" 0805_HV 3625,1275 r180 top value=47uF
C41 "GRM188R61E106MA73D" 0603 3425,1475 r270 top value=10uF
C42 "GRM155R71E104KE14D" 0402 3350,1475 r270 top value=0.1uF
C43 "GRM32ER61C476ME15L" 1210_270 3575,3760 r180 top value=47uF
C44 "GRM188R61E106MA73D" 0603 3425,3950 r270 top value=10uF
C45 "GRM155R71E104KE14D" 0402 3350,3950 r270 top value=0.1uF
C46 "GRM155R71A104KA01D" 0402 3125,3025 r180 top value=0.1uF
C47 "C2012X5R1A476M125AC" 0805_HV 3625,2850 r180 top value=47uF
C48 "GRM188R61E106MA73D" 0603 3425,3125 r270 top value=10uF
C49 "GRM155R71E104KE14D" 0402 3350,3125 r270 top value=0.1uF
C50 "GRM155R71A104KA01D" 0402 3125,2425 r180 top value=0.1uF
C51 "C2012X5R1A476M125AC" 0805_HV 3625,2350 r180 top value=47uF
C52 "GRM188R61E106MA73D" 0603 3425,2525 r270 top value=10uF
C53 "GRM155R71E104KE14D" 0402 3350,2525 r270 top value=0.1uF
C54 "GRM188R72A102KA01D" 0603L 275,2261.81 r270 top value=1000pF
C55 "GRM188R72A102KA01D" 0603L 625,2261.81 r270 top value=1000pF
C56 "GRM188R72A102KA01D" 0603 1525,3660 r270 bottom value=1000pF
C57 "GR443QR73D102KW01L" 1812 550,3336.81 r90 bottom value=1000pF
C58 "GRM188R72A103KA01D" 0603L 500,3636.81 r270 bottom value=0.01uF
C59 "GRM188R72A103KA01D" 0603L 600,3636.81 r270 bottom value=0.01uF
C60 "GRM188R72A103KA01D" 0603L 125,3661.81 r270 bottom value=0.01uF
C61 "GRM188R72A103KA01D" 0603L 200,3661.81 r270 bottom value=0.01uF
C62 "GRM155R61A105KE15D" 0402 1100,4586.81 r270 top value=1uF
C63 "GRM155R61A105KE15D" 0402 1300,4586.81 r270 top value=1uF
C64 "GRM188R71C105KE15D" 0603 625,4436.81 r270 top value=1uF
C65 "GRM188R61E106MA73D" 0603 550,4436.81 r270 top value=10uF
C66 "GRM188Z71C225KE43" 0603 875,4661.81 r270 bottom value=2.2uF
C67 "GRM188Z71C225KE43" 0603 1025,4511.81 r270 top value=2.2uF
C68 "GRM188R61E106MA73D" 0603 875,4661.81 r270 top value=10uF
C69 "GRM1555C1E471JA01D" 0402 900,4536.81 r0 top value=470pF
C70 "GCM155R71C104KA55D" 0402 575,4186.81 r270 bottom value=0.1uF
C71 "GRM188R61E106MA73D" 0603 650,4186.81 r270 top value=10uF
C72 "GRM155R61A105KE15D" 0402 1100,4461.81 r270 top value=1uF
C73 "GRM155R61A105KE15D" 0402 1300,4461.81 r270 top value=1uF
C74 "GRM188R72A102KA01D" 0603 1600,3660 r270 bottom value=1000pF
C75 "GRM188R72A102KA01D" 0603 1525,3390 r270 bottom value=1000pF
C76 "GRM155R71A104KA01D" 0402 1975,1100 r90 top value=0.1uF
C77 "GRM21BR71A106ME51L" 0805_HV 2850,825 r90 top value=10uF
C78 "GRM1555C1H750JA01D" 0402 2200,1100 r90 top value=75pF
C79 "GRM21BR71C475KA73L" 0805_HV 2575,825 r90 top value=4.7uF
C80 "GRM155R71E104KE14D" 0402 2650,825 r90 top value=0.1uF
C81 "GRM32ER61C476ME15L" 1210_270 2415,600 r90 top value=47uF
C82 "GRM32ER61C476ME15L" 1210_270 2550,600 r90 top value=47uF
C83 "GRM188R61E106MA73D" 0603 2225,925 r270 top value=10uF
C84 "GRM188R61E106MA73D" 0603 2225,925 r270 bottom value=10uF
C85 "GRM155R71E104KE14D" 0402 2100,875 r180 top value=0.1uF
C86 "GRM31CR61C226ME15L" 1206_180 3275,825 r90 top value=22uF
C87 "GRM21BR71C475KA73L" 0805_HV 3000,825 r90 top value=4.7uF
C88 "GRM155R71E104KE14D" 0402 3075,825 r90 top value=0.1uF
C89 "GRM31CR61C226ME15L" 1206_180 3700,825 r90 top value=22uF
C90 "GRM21BR71C475KA73L" 0805_HV 3425,825 r90 top value=4.7uF
C91 "GRM155R71E104KE14D" 0402 3500,825 r90 top value=0.1uF
C92 "GRM21BR71A106ME51L" 0805_HV 4125,825 r90 top value=10uF
C93 "GRM21BR71C475KA73L" 0805_HV 3850,825 r90 top value=4.7uF
C94 "GRM155R71E104KE14D" 0402 3925,825 r90 top value=0.1uF
C95 "GRM155R71E104KE14D" 0402 3549.02,3446.81 r180 top value=0.1uF
C96 "GRM155R61A105KE15D" 0402 3875,3690 r180 top value=1uF
C97 "GRM155R61A105KE15D" 0402 3875,3560 r180 top value=1uF
C98 "GRM155R61A105KE15D" 0402 3875,2810 r0 top value=1uF
C99 "GRM188R71C105KA12D" 0603 3910,4325 r180 top value=1uF
C100 "GRM155R61A105KE15D" 0402 3875,2940 r0 top value=1uF
C101 "GRM188R71C105KA12D" 0603 3910,4180 r180 top value=1uF
C102 "GRM155R61A105KE15D" 0402 3875,2410 r0 top value=1uF
C103 "GRM155R61A105KE15D" 0402 3875,2540 r0 top value=1uF
C104 "C1005NP01H102J050BA" 0402 1175,4800 r270 top value=1000pF
C105 "GRM188R71H224KAC4D" 0603 1050,4136.81 r180 bottom value=0.22uF
C106 "GRM188R71E474KA12D" 0603 1925,4511.81 r0 bottom value=0.47uF
C107 "C1608X5R1V475K080AC" 0603 1200,4086.81 r90 top value=4.7uF
C108 "GRM188R71H224KAC4D" 0603 1050,4061.81 r180 bottom value=0.22uF
C109 "EMZA350ADA100ME61G" CAPSMT_62_E61 1290,4736.81 r0 bottom value=10uF
C110 "GRM155R71C104KA88D" 0402 1650,3911.81 r180 bottom value=0.1uF
C111 "GRM155R71C104KA88D" 0402 1775,4636.81 r270 bottom value=0.1uF
C112 "GRM155R71C104KA88D" 0402 1625,4636.81 r270 bottom value=0.1uF
C113 "GRM1555C1H100RA01D" 0402 775,4386.81 r90 top value=10pF
C114 "GRM1555C1H100RA01D" 0402 775,4281.81 r270 top value=10pF
C115 "GRM155R71C104KA88D" 0402 2150,3811.81 r270 top value=0.1uF
C116 "CL05A106MP8NUB8" 0402 2000,3811.81 r90 top value=10uF
C117 "GRM155R71C104KA88D" 0402 2400,3561.81 r90 top value=0.1uF
C118 "CL05A106MP8NUB8" 0402 2450,3561.81 r270 bottom value=10uF
C119 "GRM155R61A105KE15D" 0402 2100,3811.81 r90 top value=1uF
C120 "GRM155R61A105KE15D" 0402 2050,3811.81 r90 top value=1uF
C121 "GRM155R61A105KE15D" 0402 2450,3561.81 r270 top value=1uF
C122 "GRM155R61A105KE15D" 0402 2400,3561.81 r270 bottom value=1uF
C123 "GRM155R71H103KA88D" 0402L 1350,4661.81 r0 top value=0.01uF
C124 "GRM1555C1H220JA01D" 0402 2075,3411.81 r270 top value=22pF
C125 "1812GC472KAT1A" 1812_254 775,4000 r270 bottom value=4700pF
C126 "1812GC472KAT1A" 1812_254 775,4000 r270 top value=4700pF
C127 "GRM1555C1H220JA01D" 0402 2325,3411.81 r270 top value=22pF
C128 "GRM155R71E104KE14D" 0402 675,975 r90 top value=0.1uF
C129 "GRM188R71C105KA12D" 0603 1300,600 r0 top value=1uF
C130 "GRM188R71C105KA12D" 0603 1300,745 r0 top value=1uF
C131 "GRM188R71C105KA12D" 0603 1550,600 r0 top value=1uF
C132 "GRM188R71C105KA12D" 0603 1050,605 r0 top value=1uF
C133 "GRM188R71C105KA12D" 0603 1550,750 r0 top value=1uF
C134 "GRM188R71C105KA12D" 0603 1050,745 r0 top value=1uF
C135 "GRM188R71C105KA12D" 0603 1800,600 r0 top value=1uF
C136 "GRM188R71C105KA12D" 0603 1800,750 r0 top value=1uF
C137 "GRM155R71A104KA01D" 0402 450,600 r180 top value=0.1uF
C138 "C3216X5R1E336M160AC" 1206_180 300,550 r90 top value=33uF
C139 "GRM188R61E106MA73D" 0603 550,900 r180 top value=10uF
C140 "GRM155R71E104KE14D" 0402 550,825 r180 top value=0.1uF
C141 "GRM155R71A823KA01D" 0402 375,750 r90 top value=0.082uF
C142 "GRM188R72A102KA01D" 0603 1600,3390 r270 bottom value=1000pF
D1 "PDS360-13" PowerDI5 1700,1461.81 r270 top value=60V
D2 "RF071M2S" SOD-123 1575,2611.81 r0 top value=200V
D3 "MMSD4148T1G" SOD-123 1900,1566.81 r180 bottom value=100V
D4 "MMSD4148T1G" SOD-123 2300,2361.81 r180 top value=100V
D5 "B230-13-F" SMB 1150,1775 r180 top value=30V
D6 "MMSD4148T1G" SOD-123 1325,3086.81 r90 bottom value=100V
D7 "MMSD4148T1G" SOD-123 1199,1269.8 r180 bottom value=100V
D8 "MMSZ5235B-7-F" SOD-123 1100,1750 r180 bottom value=6.8V
D9 "HD04-T" MiniDIP 824.99,2861.81 r90 top value=400V
D10 "SMAJ58A" SMA 1625,3161.81 r0 top value=58V
D11 "HD04-T" MiniDIP 600,2861.81 r90 top value=400V
D12 "SBR0220T5-7-F" SOD-523 400,4196.81 r180 bottom value=20V
D13 "D5V0M1U2LP3-7" X3-DFN0603-2 525,4211.81 r270 bottom value=5.5V
D14 "SMAJ13CA" SMA 650,1511.81 r90 bottom value=13V
EARTH "TESTPOINT" Keystone_5019 250,3150 r180 top
F1 "3413.0112.24" Fuse_USF1206 675,1686.81 r180 top
F2 "3413.0113.11" Fuse_USF1206 375,2586.81 r90 top
GND "TESTPOINT" Keystone_5019 4100,4085 r180 top
GND "TESTPOINT" Keystone_5019 3188,405 r90 top
GND "TESTPOINT" Keystone_5019 2840,405 r90 top
GND "TESTPOINT" Keystone_5019 1440,400 r90 top
GND "TESTPOINT" Keystone_5019 4100,1635 r0 top
GND "TESTPOINT" Keystone_5019 4100,2335 r0 top
GND "TESTPOINT" Keystone_5019 4100,1985 r0 top
GND "TESTPOINT" Keystone_5019 4100,2690 r180 top
GND "TESTPOINT" Keystone_5019 3538,400 r90 top
GND "TESTPOINT" Keystone_5019 3888,400 r90 top
GND "TESTPOINT" Keystone_5019 2488,400 r270 top
GND "TESTPOINT" Keystone_5019 4100,3740 r180 top
GND "TESTPOINT" Keystone_5019 4100,3040 r180 top
GND "TESTPOINT" Keystone_5019 375,975 r180 top
GND "TESTPOINT" Keystone_5019 4100,4435 r180 top
GND "TESTPOINT" Keystone_5019 2140,400 r270 top
GND "TESTPOINT" Keystone_5019 1790,400 r90 top
GND "TESTPOINT" Keystone_5019 1090,400 r90 top
GND "TESTPOINT" Keystone_5019 4100,3390 r180 top
H1 "NY PMS 440 0025 PH" "NY PMS 440 0025 PH" 190,4691.81 r0 top locked
H2 "NY PMS 440 0025 PH" "NY PMS 440 0025 PH" 4297,4690 r0 top locked
H3 "NY PMS 440 0025 PH" "NY PMS 440 0025 PH" 4250,200 r0 top locked
H4 "NY PMS 440 0025 PH" "NY PMS 440 0025 PH" 190,190 r0 top locked
H5 "1902C" Keystone_1902C 190,4691.81 r180 bottom locked
H6 "1902C" Keystone_1902C 4297,4690 r180 bottom locked
H7 "1902C" Keystone_1902C 4250,200 r180 bottom locked
H8 "1902C" Keystone_1902C 190,190 r180 bottom locked
J1 "ED555/2DS" TERM_BLK_ED555-2DS 150,1100 r270 top
J2 "PJ-202AH" CONN_CUI-PJ-202AH 541.22,1711.81 r180 top
J3 "TSW-103-07-G-S" TSW-103-07-X-S 2200,3111.81 r0 top
J4 "TSW-102-07-G-S" TSW-102-07-G-S 3000,2200 r90 top
J5 "HTSW-103-07-G-S" Samtec_HTSW-103-07-G-S 2800,4085 r270 top
J6 "TSW-102-07-G-S" TSW-102-07-G-S 3074.02,4321.81 r180 top
J7 "TSW-102-07-G-S" TSW-102-07-G-S 3000,4700 r90 top
J8 "GRPB052VWVN-RC" CONN_GRPB052VWVN-RC 3824.02,4776.81 r0 top
J9 "ED555/2DS" TERM_BLK_ED555-2DS 4350,1850 r90 top
J10 "TSW-102-07-G-S" TSW-102-07-G-S 2999.02,1675 r90 top
J11 "TSW-102-07-G-S" TSW-102-07-G-S 3000,4150 r90 top
J12 "ED555/2DS" TERM_BLK_ED555-2DS 4350,1500 r90 top
J13 "ED555/2DS" TERM_BLK_ED555-2DS 4350,3950 r90 top
J14 "TSW-102-07-G-S" TSW-102-07-G-S 3000,3325 r90 top
J15 "ED555/2DS" TERM_BLK_ED555-2DS 4350,3250 r90 top
J16 "TSW-102-07-G-S" TSW-102-07-G-S 3000,2725 r90 top
J17 "ED555/2DS" TERM_BLK_ED555-2DS 4350,2200 r90 top
J18 "1-406541-1" TEC_1-406541-1 325,3661.81 r270 top
J19 "10118194-0001LF" FCI_10118194-0001LF 50,4311.81 r90 bottom
J20 "HTSW-103-07-G-S" Samtec_HTSW-103-07-G-S 2725,4806 r180 top
J22 "TSW-102-07-G-S" TSW-102-07-G-S 2725,1075 r180 top
J23 "TSW-102-07-G-S" TSW-102-07-G-S 2425,1075 r180 top
J24 "ED555/2DS" TERM_BLK_ED555-2DS 2700,150 r0 top
J25 "ED555/2DS" TERM_BLK_ED555-2DS 2350,150 r0 top
J26 "TSW-102-07-G-S" TSW-102-07-G-S 3025,1075 r180 top
J27 "ED555/2DS" TERM_BLK_ED555-2DS 3050,150 r0 top
J28 "TSW-102-07-G-S" TSW-102-07-G-S 3325,1075 r180 top
J29 "ED555/2DS" TERM_BLK_ED555-2DS 3400,150 r0 top
J30 "TSW-102-07-G-S" TSW-102-07-G-S 3675,1075 r0 top
J31 "ED555/2DS" TERM_BLK_ED555-2DS 3750,150 r0 top
J32 "TSW-102-07-G-S" TSW-102-07-G-S 3874.56,3362.02 r90 top
J33 "TSW-102-07-G-S" TSW-102-07-G-S 1325,1075 r0 top
J34 "ED555/2DS" TERM_BLK_ED555-2DS 4350,3600 r90 top
J35 "TSW-102-07-G-S" TSW-102-07-G-S 3875,3125 r270 top
J36 "ED555/2DS" TERM_BLK_ED555-2DS 1300,150 r0 top
J37 "TSW-102-07-G-S" TSW-102-07-G-S 3875,3975 r90 top
J38 "TSW-102-07-G-S" TSW-102-07-G-S 1075,1075 r0 top
J39 "ED555/2DS" TERM_BLK_ED555-2DS 4350,2900 r90 top
J40 "ED555/2DS" TERM_BLK_ED555-2DS 4350,4300 r90 top
J41 "TSW-102-07-G-S" TSW-102-07-G-S 3875,2670 r270 top
J42 "TSW-102-07-G-S" TSW-102-07-G-S 1575,1075 r0 top
J43 "ED555/2DS" TERM_BLK_ED555-2DS 4350,2550 r90 top
J44 "TSW-102-07-G-D" TSW-102-07-G-D 1035,4761.81 r0 top
J45 "PRPC010DAAN-RC" Sullins_xxxC010DAAN 1950,4761.81 r270 top
J47 "5-1814832-1" TE_5-1814832-1 2725,3725 r270 top
J48 "HTSW-103-07-G-S" Samtec_HTSW-103-07-G-S 2800,4425 r270 top
J49 "HTSW-102-07-G-S" Samtec_HTSW-102-07-G-S 2000,4036.81 r270 top
J50 "5-1814832-1" TE_5-1814832-1 2725,3385 r0 top
J51 "HTSW-102-07-G-S" Samtec_HTSW-102-07-G-S 2600,4036.81 r90 top
J52 "HTSW-102-07-G-S" Samtec_HTSW-102-07-G-S 2475,4036.81 r90 top
J53 "HTSW-102-07-G-S" Samtec_HTSW-102-07-G-S 2350,4036.81 r90 top
J54 "ED555/2DS" TERM_BLK_ED555-2DS 1650,150 r0 top
J55 "ED555/2DS" TERM_BLK_ED555-2DS 950,150 r0 top
J56 "TSW-102-07-G-S" TSW-102-07-G-S 1825,1075 r0 top
J57 "ED555/2DS" TERM_BLK_ED555-2DS 2000,150 r0 top
J58 "TSW-102-07-G-S" TSW-102-07-G-S 825,600 r270 top
J59 "TSW-102-07-G-S" TSW-102-07-G-S 575,1050 r270 top locked
J60 "GRPB052VWVN-RC" CONN_GRPB052VWVN-RC 125,550 r90 top
L1 "ME3220-332MLB" ME3220 1175,2561.81 r0 top value=3.3uH
L2 "" 0603 850,1686.81 r0 top value="220 ohm"
L3 "DLW5BTM142TQ2L" DLW5BT_TQ2 850,1511.81 r90 top
L4 "" 0603 850,1336.81 r0 top value="220 ohm"
L5 "LQH5BPN4R7N38L" LQH5BPN_38 3600,2000 r0 top value=4.7uH
L6 "LPS8045B-154MRB" LPS8045B 3600,4400 r0 top value=150uH
L7 "1255AY-100M=P3" IND_1255AY 3600,1475 r0 top value=10uH
L8 "XFL5030-472MEC" XFL5030 3575,3950 r0 top value=4.7uH
L9 "SRT8045-103MEB" SRT8045 3625,3125 r0 top value=15uH
L10 "XFL5030-472MEC" XFL5030 3600,2525 r0 top value=2.2uH
L11 "ACT45L-201-2P-TL000" TDK_ACT45L 1750,3536.81 r0 top value=200uH
L12 "" 0603 450,2411.81 r0 top value="330 ohm"
L13 "ACT45L-201-2P-TL000" TDK_ACT45L 1750,3786.81 r0 top value=200uH
L14 "DLW44SM242SK2L" MuRata_DLW44SN 450,2261.81 r90 top
L15 "" 0603 450,2111.81 r0 top value="330 ohm"
L16 "BLM18AG102SN1D" 0603 1200,4586.81 r0 top value="1000 ohm"
L17 "BLM18AG102SN1D" 0603 1200,4461.81 r0 top value="1000 ohm"
L18 "XEL4030-222MEB" XEL4030_310 2750,625 r0 top value=2.2uH
L19 "SRT8045-103MEB" SRT8045 2125,675 r270 top value=10uH
L20 "1217AS-H-150M=P3" DEM8045C 550,400 r180 top value=15uH
L21 "XEL4030-102MEB" XEL4030_310 3175,625 r0 top value=1uH
L22 "XEL4030-102MEB" XEL4030_310 3600,625 r0 top value=1uH
L23 "XEL4030-222MEB" XEL4030_310 4025,625 r0 top value=2.2uH
LED0_H "QTLP630C4TR" QTLP630C_Green 2575,4535 r270 top value=Green
LED0_L "QTLP630C4TR" QTLP630C_Green 2675,4535 r270 top value=Green
LED2_H "QTLP630C4TR" QTLP630C_Green 2375,4535 r90 top value=Green
LED2_L "QTLP630C4TR" QTLP630C_Green 2475,4535 r270 top value=Green
Logo2 "Pb-Free Symbol" Pb-Free_Overlay_Small 2786,1922 r0 top
Logo3 "FCC disclaimer" FCC_disclaimer 2350,3491.81 r0 top
Loop "TESTPOINT" Keystone_5019 1225,2836.81 r90 top
MCU_LEDs "HSMF-C165" HSMF-C165_RG 2100,4261.81 r270 top value=Rg
PGND "TESTPOINT" Keystone_5019 2450,2700 r90 top
Q1 "2N7002" SOT-23 2400,1411.81 r0 bottom value=60V
R1 "CRCW080539K0JNEA" 0805_HV 1375,2611.81 r180 top value=39k
R2 "CRCW120624R0JNEA" 1206 1520,1585 r180 top value=24
R3 "RC0805FR-0710RL" 0805L 2250,2211.81 r270 top value=10.0
R4 "CRCW06038K06FKEA" 0603 1080,1340 r270 top value=8.06k
R5 "CRCW06034K02FKEA" 0603L 2450,2211.81 r90 top value=4.02k
R6 "CRCW2512100RJNEG" 2512 2200,1561.81 r180 bottom value=100
R7 "CRCW060311K5FKEA" 0603 2200,1211.81 r180 bottom value=11.5k
R8 "MCT06030Z0000ZP500" 0603 1425,3061.81 r90 bottom value=0
R9 "CRCW060310K0FKEA" 0603 2200,1361.81 r0 bottom value=10.0k
R10 "CRM0805-FX-R910ELF" 0805L 1850,2536.81 r180 top value=0.91
R11 "CRM0805-FX-R910ELF" 0805L 1850,2611.81 r180 top value=0.91
R12 "CRCW040224K9FKED" 0402L 1525,2931.81 r180 top value=24.9k
R13 "ERJ-2RKF1001X" 0402L 1975,2486.81 r180 top value=1.00k
R14 "RMCF0402FT49R9" 0402L 1325,2911.81 r270 top value=49.9
R15 "CRCW040224K9FKED" 0402L 1375,2911.81 r90 top value=24.9k
R16 "CRCW040247K0JNED" 0402L 1325,2811.81 r270 top value=47k
R17 "CRCW0603649RFKEA" 0603 1800,3011.81 r180 top value=649
R18 "CRCW04028K66FKED" 0402L 1500,2836.81 r0 top value=8.66k
R19 "RC0402JR-070RL" 0402L 1850,2686.81 r270 bottom value=0
R20 "CRCW060310K0FKEA" 0603 1250,1290 r270 top value=10.0k
R21 "CRCW04026K49FKED" 0402L 1425,2911.81 r270 top value=6.49k
R22 "3314J-1-101E" Bourns_3314J-1 2200,2911.81 r270 top value="100 ohm"
R23 "CRCW040210R0JNED" 0402L 1975,2811.81 r0 top value=10
R24 "CRCW0402237KFKED" 0402L 1975,3036.81 r0 top value=237k
R25 "3314J-1-200E" Bourns_3314J-1 2200,2661.81 r270 top value="20 ohm"
R26 "CRCW040210R0JNED" 0402L 1975,2761.81 r0 top value=10
R27 "CRCW06032K00JNEA" 0603L 1133.07,1368 r90 bottom value=2.0k
R28 "CRCW040260K4FKED" 0402L 1975,2986.81 r180 top value=60.4k
R29 "RC0603FR-07100KL" 0603L 1235,1201 r0 bottom value=100k
R30 "CRCW04024K42FKED" 0402 3000,2050 r180 top value=4.42k
R31 "CRCW04020000Z0ED" 0402 3350,4275 r0 top value=0
R32 "CRCW040210K0FKED" 0402 3000,2000 r0 top value=10.0k
R33 "CRCW0402910RJNED" 0402 3100,4450 r90 top value=910
R34 "CRCW12067R87FKEA" 1206 3025,4475 r90 top value=7.87
R35 "CRCW04027K68FKED" 0402 3000,1525 r180 top value=7.68k
R36 "CRCW040256K2FKED" 0402 3000,4000 r180 top value=56.2k
R37 "CRCW040210K0FKED" 0402 3000,1475 r0 top value=10.0k
R38 "CRCW040210K0FKED" 0402 3000,3950 r0 top value=10.0k
R39 "CRCW040233K2FKED" 0402 3000,3175 r180 top value=33.2k
R40 "CRCW040210K0FKED" 0402 3000,3125 r0 top value=10.0k
R41 "CRCW040213K3FKED" 0402 3000,2575 r180 top value=13.3k
R42 "CRCW040210K0FKED" 0402 3000,2525 r0 top value=10.0k
R43 "CRCW040268K1FKED" 0402 1340,1540 r90 top value=68.1k
R44 "CRCW040227K4FKED" 0402 1175,1585 r90 top value=27.4k
R45 "CRCW060375R0FKEA" 0603L 500,3536.81 r90 bottom value=75.0
R46 "CRCW060375R0FKEA" 0603L 600,3536.81 r90 bottom value=75.0
R47 "CRCW060375R0FKEA" 0603L 125,3561.81 r90 bottom value=75.0
R48 "CRCW060375R0FKEA" 0603L 200,3561.81 r90 bottom value=75.0
R49 "CRCW04020000Z0ED" 0402 525,4636.81 r90 top value=0
R50 "CRCW0402100KDHEDP" 0402 770,4486.81 r180 top value=100k
R51 "CRCW0402470RJNED" 0402 550,4828 r0 bottom value=470
R52 "CRCW04020000Z0ED" 0402 575,4636.81 r270 top value=0
R53 "CRCW0402165KFKED" 0402 900,4486.81 r180 top value=165k
R54 "CRCW040233R0JNED" 0402 285,4385 r270 bottom value=33
R55 "CRCW0402510KJNED" 0402 2175,975 r90 bottom value=510k
R56 "CRCW0402442KFKED" 0402 2725,975 r0 top value=442k
R57 "CRCW0402100KDHEDP" 0402 2200,1100 r270 bottom value=100k
R58 "CRCW040297K6FKED" 0402 2725,925 r180 top value=97.6k
R59 "CRCW040213K7FKED" 0402 2250,1100 r90 top value=13.7k
R60 "CRCW0402100KDHEDP" 0402 3150,975 r0 top value=100k
R61 "CRCW0402120KFKED" 0402 3150,925 r180 top value=120k
R62 "CRCW0402124KFKED" 0402 3575,975 r0 top value=124k
R63 "CRCW0402100KDHEDP" 0402 3575,925 r180 top value=100k
R64 "CRCW0402196KFKED" 0402 4000,975 r0 top value=196k
R65 "CRCW040297K6FKED" 0402 4000,925 r180 top value=97.6k
R66 "CRCW0402100KJNED" 0402 3399.02,3450 r180 top value=100k
R67 "CRCW0402100KJNED" 0402 3400,3550 r180 top value=100k
R68 "CRCW0402100KJNED" 0402 3400,3600 r180 top value=100k
R69 "RC0201JR-07470RL" 0201 2075,4361.81 r90 top value=470
R70 "RC0201JR-07470RL" 0201 2125,4361.81 r90 top value=470
R71 "ERJ-1GE0R00C" 0201M 1775,3881.81 r90 bottom value=0
R72 "ERJ-1GE0R00C" 0201M 1725,3881.81 r90 bottom value=0
R73 "CRCW04020000Z0ED" 0402 1200,4336.81 r0 bottom value=0
R74 "CRCW040247K0JNED" 0402 1175,4685 r90 top value=47k
R75 "CRCW04021K40FKED" 0402 825,4386.81 r270 top value=1.40k
R76 "CRCW04021M00FKED" 0402 875,4386.81 r270 top value=1.00Meg
R77 "CRCW04020000Z0ED" 0402 1700,4636.81 r180 bottom value=0
R78 "CRCW040227R0JNED" 0402 675,4311.81 r180 bottom value=27
R79 "CRCW040227R0JNED" 0402 675,4361.81 r180 bottom value=27
R80 "CRCW04020000Z0ED" 0402 2400,4586.81 r270 bottom value=0
R81 "CRCW04020000Z0ED" 0402 2300,4586.81 r270 top value=0
R82 "CRCW04020000Z0ED" 0402 2250,4586.81 r270 bottom value=0
R83 "CRCW04020000Z0ED" 0402 2175,4586.81 r270 bottom value=0
R84 "CRCW04020000Z0ED" 0402 2100,4586.81 r270 bottom value=0
R85 "CRCW04020000Z0ED" 0402 1850,4586.81 r270 top value=0
R86 "CRCW04020000Z0ED" 0402 2025,4586.81 r270 bottom value=0
R87 "CRCW04020000Z0ED" 0402 1600,4586.81 r270 top value=0
R88 "CRCW04020000Z0ED" 0402 1500,4586.81 r270 top value=0
R89 "CRCW04020000Z0ED" 0402 2700,4385 r90 bottom value=0
R90 "CRCW04020000Z0ED" 0402 2650,4385 r90 bottom value=0
R91 "CRCW04022K20JNED" 0402 2500,3561.81 r270 top value=2.2k
R92 "CRCW04026K49FKED" 0402 2400,3400 r270 top value=6.49k
R93 "CRCW02012K20JNED" 0201M 1250,4661.81 r180 top value=2.2k
R94 "CRCW04020000Z0ED" 0402 2725,3825 r270 bottom value=0
R95 "CRCW0402470RJNED" 0402 2650,4685 r90 top value=470
R96 "CRCW04022K49FKED" 0402 2700,4685 r90 top value=2.49k
R97 "CRCW0402470RJNED" 0402 2375,4400 r90 top value=470
R98 "CRCW04022K49FKED" 0402 2550,4685 r90 top value=2.49k
R99 "CRCW0402470RJNED" 0402 2600,4685 r270 top value=470
R100 "ERJ-1GE0R00C" 0201M 2125,3536.81 r0 top value=0
R101 "HVCB2010FKC1M00" 2010 1250,3300 r0 top value=1.00Meg
R102 "HVCB2010FKC1M00" 2010 1250,3300 r0 bottom value=1.00Meg
R103 "CRCW04022K49FKED" 0402 2425,4400 r270 top value=2.49k
R104 "RC0402FR-071ML" 0402 2200,3311.81 r180 top value=1.00Meg
R105 "ERJ-1GE0R00C" 0201M 2225,3536.81 r180 top value=0
R106 "CRCW04022K49FKED" 0402 1900,3961.81 r90 bottom value=2.49k
R107 "CRCW04022K49FKED" 0402 2600,4170 r90 bottom value=2.49k
R108 "ERJ-1GE0R00C" 0201 2225,3535 r90 bottom value=0
R109 "CRCW04022K49FKED" 0402 2475,4170 r90 bottom value=2.49k
R110 "CRCW04022K49FKED" 0402 2350,4150 r0 bottom value=2.49k
R111 "CRCW04020000Z0ED" 0402 3675,3550.38 r270 top value=0
R112 "CRCW04020000Z0ED" 0402 3550,3650.38 r0 top value=0
R113 "CRCW0402100KJNED" 0402 725,1125 r90 top value=100k
R114 "CRCW0402100KJNED" 0402 775,1125 r90 top value=100k
R115 "CRCW0402100KJNED" 0402 825,1125 r90 top value=100k
R116 "CRCW04020000Z0ED" 0402 775,865 r180 top value=0
R117 "CRCW04020000Z0ED" 0402 875,975 r270 top value=0
R118 "CRCW04020000Z0ED" 0402 610,600 r0 top value=0
R119 "CRCW0402910RJNED" 0402 325,750 r90 top value=910
R120 "CSR1206FKR100" 1206 150,800 r180 top value=0.1
R121 "ERJ-8CWFR033V" 1206 375,850 r0 top value=0.033
R122 "CRCW0402470RJNED" 0402 2500,4685 r90 top value=470
R123 "CRCW04022K49FKED" 0402 2500,4685 r90 bottom value=2.49k
R124 "ERJ-1GE0R00C" 0201 2175,3535 r90 bottom value=0
R125 "CRCW04024K99FKED" 0402 1290,1540 r270 top value=4.99k
R126 "CRCW12060000Z0EA" 1206 1160,1460 r0 top value=0
R127 "CRCW060391K0JNEA" 0603 1313,1290 r90 top value=91k
R128 "CRCW040268K1FKED" 0402 1445,1460 r270 top value=68.1k
R129 "CRCW04024K87FKED" 0402 1230,1585 r270 top value=4.87k
R130 "CRCW04024K99FKED" 0402 1390,1540 r270 top value=4.99k
R131 "CRCW12060000Z0EA" 1206 1841.95,1265.2 r270 bottom value=0
R132 "CRCW12060000Z0EA" 1206 1555,1422 r270 bottom value=0
RESET "B3U-1100P" SW_B3U-1100P 1300,4761.81 r0 top
RSNS "TESTPOINT" Keystone_5019 2600,2700 r90 top
SEQ1_FLAG1 "TESTPOINT" Keystone_5019 3100,3500 r180 top
SEQ1_FLAG2 "TESTPOINT" Keystone_5019 3100,3600 r180 top
SEQ1_FLAG3 "TESTPOINT" Keystone_5019 3100,3700 r180 top
SEQ2_FLAG1 "TESTPOINT" Keystone_5019 4325,625 r0 top
SEQ2_FLAG2 "TESTPOINT" Keystone_5019 4328,823 r0 top
SEQ2_FLAG3 "TESTPOINT" Keystone_5019 4331,1034 r0 top
T1 "LDT0950-50" Linkcom_LDT0937-50 1850,2011.81 r0 top value=150uH
T2 "H2019FNLT" PULSE_H2019FNL 1249.99,3661.81 r180 top value=350uH
U1 "TPS23755RJJ" RJJ0023B 1700,2811.81 r180 top
U2 "TPS2121RUXR" RUX0012A 1327.87,1414.69 r180 top
U3 "HMHA2801A" MFP04A 1000,1950 r90 bottom
U4 "TPS562208DDCR" DDC0006A_N 3150,2000 r180 top
U5 "TPS54201DDCR" DDC0006A_N 3300,4400 r180 top
U6 "TPS561208DDCR" DDC0006A_N 3150,1475 r180 top
U7 "TPS561201DDCR" DDC0006A_N 3150,3950 r180 top
U8 "TPS562201DDCR" DDC0006A_N 3150,3125 r180 top
U9 "TPS561201DDCR" DDC0006A_N 3150,2525 r180 top
U10 "TL5209DR" D0008A_N 720,4661.81 r90 top
U11 "TPD2EUSB30DRTR" DRT0003A 375,4296.81 r270 bottom
U12 "TPD1E10B06DPYR" DPY0002A 300,4221.81 r270 bottom
U13 "TLV62568DRLR" DRL0006A 2725,825 r0 top
U14 "TPS54202HDDCR" DDC0006A_N 2100,1075 r90 top
U15 "TLV62569ADRLR" DRL0006A 3150,825 r0 top
U16 "TLV62568ADRLR" DRL0006A 3575,825 r0 top
U17 "TLV62568DRLR" DRL0006A 4000,825 r0 top
U18 "LM3880MF-1AA/NOPB" MF06A_N 3550,3550 r180 top
U19 "TLV74218PDQNR" DQN0004A 3874.56,3625.21 r270 top
U20 "TLV74228PDQNR" DQN0004A 3875,2875 r90 top
U21 "TLV74233PDQNR" DQN0004A 3912.3,4254.02 r270 top
U22 "TLV74215PDQNR" DQN0004A 3875,2475 r90 top
U23 "MSP430F5529IPN" PN0080A_N 1625,4261.81 r270 bottom
U24 "TPD4E05U06DQAR" DQA0010A 2000,3661.81 r180 top
U25 "DP83825IRLLR" RLL0024A 2275,3661.81 r270 top
U26 "TLV74218PDQNR" DQN0004A 1300,675 r90 top
U27 "LM3880MF-1AA/NOPB" MF06A_N 775,975 r90 top
U28 "TLV74228PDQNR" DQN0004A 1550,675 r90 top
U29 "TLV74233PDQNR" DQN0004A 1050,675 r90 top
U30 "TLV74215PDQNR" DQN0004A 1800,675 r90 top
U31 "TPS54201DDCR" DDC0006A_N 525,700 r180 top
VBIAS "TESTPOINT" Keystone_5019 2600,2250 r90 top
VCC "TESTPOINT" Keystone_5019 2600,2450 r90 top
VLED1 "TESTPOINT" Keystone_5019 3850,4625 r180 top
VLED1_FB "TESTPOINT" Keystone_5019 3524.02,4756.81 r0 top
VLED2 "TESTPOINT" Keystone_5019 475,125 r90 top
VLED2_FB "TESTPOINT" Keystone_5019 650,125 r270 top
VPD "TESTPOINT" Keystone_5019 1050,3100 r270 top
VSS "TESTPOINT" Keystone_5019 1900,3161.81 r180 top
XTAL1 "ECS-250-12-33Q-JES-TR" ECS_ECS-33Q 2200,3411.81 r270 top
Y1 "CSTCR4M00G15L99-R0" Murata_CSTCR_G15L 1050,4291.81 r270 bottom
ZZ1 "This Assembly Note is for PCB labels only" AssemblyNoteLabel 589.11,5633.81 r0 top
ZZ2 "This Assembly Note will show in the PcbDoc and associated outputs" AssemblyNote 597.11,5536 r0 top
ZZ3 "This Assembly Note will show in the PcbDoc and associated outputs" AssemblyNote 601.11,5444 r0 top
ZZ4 "This Assembly Note will show in the PcbDoc and associated outputs" AssemblyNote 591.11,5340.81 r0 top

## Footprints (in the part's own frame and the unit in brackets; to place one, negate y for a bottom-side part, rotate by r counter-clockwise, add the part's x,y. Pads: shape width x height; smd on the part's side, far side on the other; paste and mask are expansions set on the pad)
0201 [mm] "Data from Kemet datasheet CC101_COM dated 7/28/11"
  rect 0.46x0.42 smd mask+0.048: 1(-0.33,0) 2(0.33,0)
  body extent -0.31,-0.16 0.31,0.16, height 0.26
0201M [mm] "Data from Kemet datasheet CC101_COM dated 7/28/11"
  rect 0.56x0.52 smd mask+0.048: 1(-0.38,0) 2(0.38,0)
  body extent -0.31,-0.16 0.31,0.16, height 0.26
0402 [mm] "0402 from SM-752 data"
  rect 0.8x0.6 smd: 1(-0.6,0) 2(0.6,0)
  silkscreen extent -1.22,-0.52 1.22,0.52, body extent -0.55,-0.3 0.55,0.3, height 0.6
0402L [mm] "0402 from SM-752 data"
  rect 0.6x0.5 smd: 1(-0.5,0) 2(0.5,0)
  body extent -0.55,-0.3 0.55,0.3, height 0.6
0603 [mm] "0603 from SM-752 data"
  rect 1x0.95 smd: 1(-0.8,0) 2(0.8,0)
  silkscreen extent -1.52,-0.69 1.52,0.69, body extent -0.87,-0.47 0.87,0.47, height 1
0603L [mm] "0603 from SM-752 data"
  rect 0.8x0.85 smd: 1(-0.7,0) 2(0.7,0)
  silkscreen extent -0.07,-0.33 0.07,0.33, body extent -0.87,-0.47 0.87,0.47, height 1
0805_HV [mil] "0805 with 30mil clearance between pads"
  rect 50x63 smd: 1(-40,0) 2(40,0)
  silkscreen extent -74,-40 74,40, body extent -43,-29 43,29, height 57
0805L [mm] "0805 from SM-752 data"
  rect 1.1x1.4 smd: 1(-0.75,0) 2(0.75,0)
  body extent -1.1,-0.72 1.1,0.72, height 1.45
1206 [mm] "1206 from SM-752 data"
  rect 1.3x1.85 smd: 1(-1.45,0) 2(1.45,0)
  silkscreen extent -2.4,-1.21 2.4,1.21, body extent -1.7,-0.9 1.7,0.9, height 1.35
1206_180 [mm] "1206_180"
  rect 1.1x1.6 smd: 1(-1.7,0) 2(1.7,0)
  silkscreen extent -0.9,-1 0.9,1, body extent -1.75,-0.95 1.75,0.95, height 1.8
1210_270 [mm] "1210"
  rect 1.3x2.7 smd: 1(-1.45,0) 2(1.45,0)
  silkscreen extent -2.32,-1.57 2.32,1.57, body extent -1.7,-1.35 1.7,1.35, height 2.7
1210_270L [mm] "1210"
  rect 1.1x2.6 smd: 1(-1.35,0) 2(1.35,0)
  silkscreen extent -0.4,-1.2 0.4,1.2, body extent -1.7,-1.35 1.7,1.35, height 2.7
1812 [mm]
  rect 1.6x3.4 smd: 1(-2,0) 2(2,0)
  silkscreen extent -0.8,-1.6 0.8,1.6, body extent -2.4,-1.7 2.4,1.7, height 1.35
1812_254 [mm] "SMD, 2-Leads, Body 4.8x3.4mm"
  rect 1.6x3.4 smd: 1(-2,0) 2(2,0)
  silkscreen extent -0.8,-1.7 0.8,1.7, body extent -2.4,-1.7 2.4,1.7, height 2.54
2010 [mm] "Chip Capacitor, Body 5.08x2.54mm, IPC Medium Density"
  rect 1.6x2.7 smd: 1(-2.3,0) 2(2.3,0)
  silkscreen extent -3.42,-1.65 3.42,1.65, body extent -2.73,-1.45 2.73,1.45, height 1.66
2512 [mm] "Chip Resistor, Body 6.3x3.2mm, IPC Medium Density"
  rect 1.3x3.4 smd: 1(-2.95,0) 2(2.95,0)
  silkscreen extent -1.9,-1.6 1.9,1.6, body extent -3.22,-1.67 3.22,1.67, height 0.71
AssemblyNote [mil] "Assembly Note"
AssemblyNoteLabel [mil] "Assembly Note for PCB Labels"
Bourns_3314J-1 [mm] "SMD, 3-Leads, Body 5x4.5mm"
  rrect8% 1.3x2 smd: 1(-1.15,2) 3(1.15,2)
  rrect5% 2x2 smd: 2(0,-2)
  silkscreen extent -2.5,-2.24 2.5,2.24, body extent -2.5,-2.5 2.5,2.5, height 2.73
CAPSMT_62_E61 [mm] "5 x 5.8mm:  Chemi-Con E61"
  rect 3x1.6 smd: 1(-2.2,0) 2(2.2,0)
  silkscreen extent -2.75,-2.75 2.75,2.75, body extent -2.75,-2.75 2.75,2.75, height 6.1
CONN_CUI-PJ-202AH [mm] "Conn_DC Jack"
  oval 1.5x4 hole 1 slot 3.5 at 90 deg: 1(0,0) 2(6,0)
  oval 4x1.5 hole 1 slot 3.5 at 0 deg: 3(3,4.7)
  silkscreen extent -0.7,-4.5 13.7,4.5, body extent -0.7,-4.5 13.7,4.9, height 11.02
CONN_GRPB052VWVN-RC [mm] "SULLINS"
  rect 1x1 hole 0.7 mask+0.08: 1(-2.54,-0.635)
  round 1 hole 0.7 mask+0.08: 2(-2.54,0.635) 3(-1.27,-0.635) 4(-1.27,0.635) 5(0,-0.635) 6(0,0.635) 7(1.27,-0.635) 8(1.27,0.635) 9(2.54,-0.635) 10(2.54,0.635)
  silkscreen extent -3.7,-1.8 3.3,1.7, body extent -3.17,-1.7 3.17,1.7, height 4
D0008A_N [mm] "SOIC, 8-Leads, Body 4.9x3.9mm, Pitch 1.27mm, IPC Medium Density"
  oval 1.45x0.6 smd: 1(-2.725,1.905) 2(-2.725,0.635) 3(-2.725,-0.635) 4(-2.725,-1.905) 5(2.725,-1.905) 6(2.725,-0.635) 7(2.725,0.635) 8(2.725,1.905)
  silkscreen extent -3.3,-2.5 0.9,2.5, body extent -3,-2.45 3,2.45, height 1.63
DDC0006A_N [mm]
  rrect17% 1x0.6 smd: 1(-1.375,0.95) 2(-1.375,0) 3(-1.375,-0.95) 4(1.375,-0.95) 5(1.375,0) 6(1.375,0.95)
  silkscreen extent -1.75,-1.52 0.7,1.53, body extent -1.43,-1.48 1.43,1.49, height 0.92
DEM8045C [mm] "SMD, 2-Leads, Body 8x8mm, Pitch 6.75 mm"
  rrect6% 1.75x3 smd: 1(-3.375,0) 2(3.375,0)
  body extent -4.15,-4.15 4.15,4.15, height 4.5
DLW5BT_TQ2 [mm] "SMD, 4-Leads, Body 5x5mm"
  rect 0.5x0.5 smd: 1(-1.2,1) 2(-1.2,-1) 3(1.2,-1) 4(1.2,1)
  Top Layer region: 2.35,0.45 0.65,0.45 0.65,1.45 1.65,1.45 1.65,2.75 2.35,2.75
  Top Layer region: 2.35,-0.45 0.65,-0.45 0.65,-1.45 1.65,-1.45 1.65,-2.75 2.35,-2.75
  Top Layer region: -2.35,0.45 -0.65,0.45 -0.65,1.45 -1.65,1.45 -1.65,2.75 -2.35,2.75
  Top Layer region: -2.35,-0.45 -0.65,-0.45 -0.65,-1.45 -1.65,-1.45 -1.65,-2.75 -2.35,-2.75
  silkscreen extent -2.65,-2.65 2.65,3.2, body extent -2.65,-2.65 2.65,2.65, height 2.51
DPY0002A [mm] "R-PX2SON-N2"
  rect 0.6x0.5 smd: 1(-0.5,0) 2(0.5,0)
  body extent -0.55,-0.35 0.55,0.35, height 0.4
DQA0010A [mm] "SON, 10-Leads, Body 1x2.5mm, Pitch 0.5mm, TI Recommended"
  rrect50% 0.565x0.2 smd: 1(-0.417,1) 2(-0.417,0.5) 4(-0.417,-0.5) 5(-0.417,-1) 6(0.417,-1) 7(0.417,-0.5) 9(0.417,0.5) 10(0.417,1)
  rrect28% 0.565x0.36 on Top Paste: 3(-0.417,0) 8(0.417,0)
  rrect25% 0.565x0.4 smd paste-0.2: 3(-0.417,0) 8(0.417,0)
  silkscreen extent -0.67,-1.45 0.55,1.45, body extent -0.55,-1.3 0.55,1.3, height 0.56
DQN0004A [mm] "SON, 0.65mm pitch"
  rect 0.25x0.31 smd paste-1 mask-0.31: 1(-0.535,0.325) 2(-0.535,-0.325) 3(0.535,-0.325) 4(0.535,0.325)
  rect 0.58x0.58 smd rot 45 paste-0.065 mask-0.05: 5(0,0)
  silkscreen extent -0.88,-0.7 0.88,0.7, body extent -0.53,-0.53 0.53,0.53, height 0.42
DRL0006A [mm] "SOTFL, 6-Flat Leads, Body 1.2x1.6x0.6mm, Pitch 0.5mm, TI recommended"
  rrect33% 0.67x0.3 smd: 1(-0.74,0.5) 2(-0.74,0) 3(-0.74,-0.5) 4(0.74,-0.5) 5(0.74,0) 6(0.74,0.5)
  silkscreen extent -0.9,-0.95 0.5,0.95, body extent -0.8,-0.8 0.8,0.8, height 0.61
